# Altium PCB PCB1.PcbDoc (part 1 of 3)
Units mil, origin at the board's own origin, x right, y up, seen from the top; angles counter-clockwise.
Board outline 6299 x 3937 mil, 12 copper layers (TopLayer, VCC, GROUND, MidLayer1, MidLayer2, MidLayer3, MidLayer4, MidLayer5, MidLayer6, MidLayer7, MidLayer8, BottomLayer); 299 components, 467 nets, 2148 pads, 429 vias.
Unrouted connection lines stored in the file: 461.
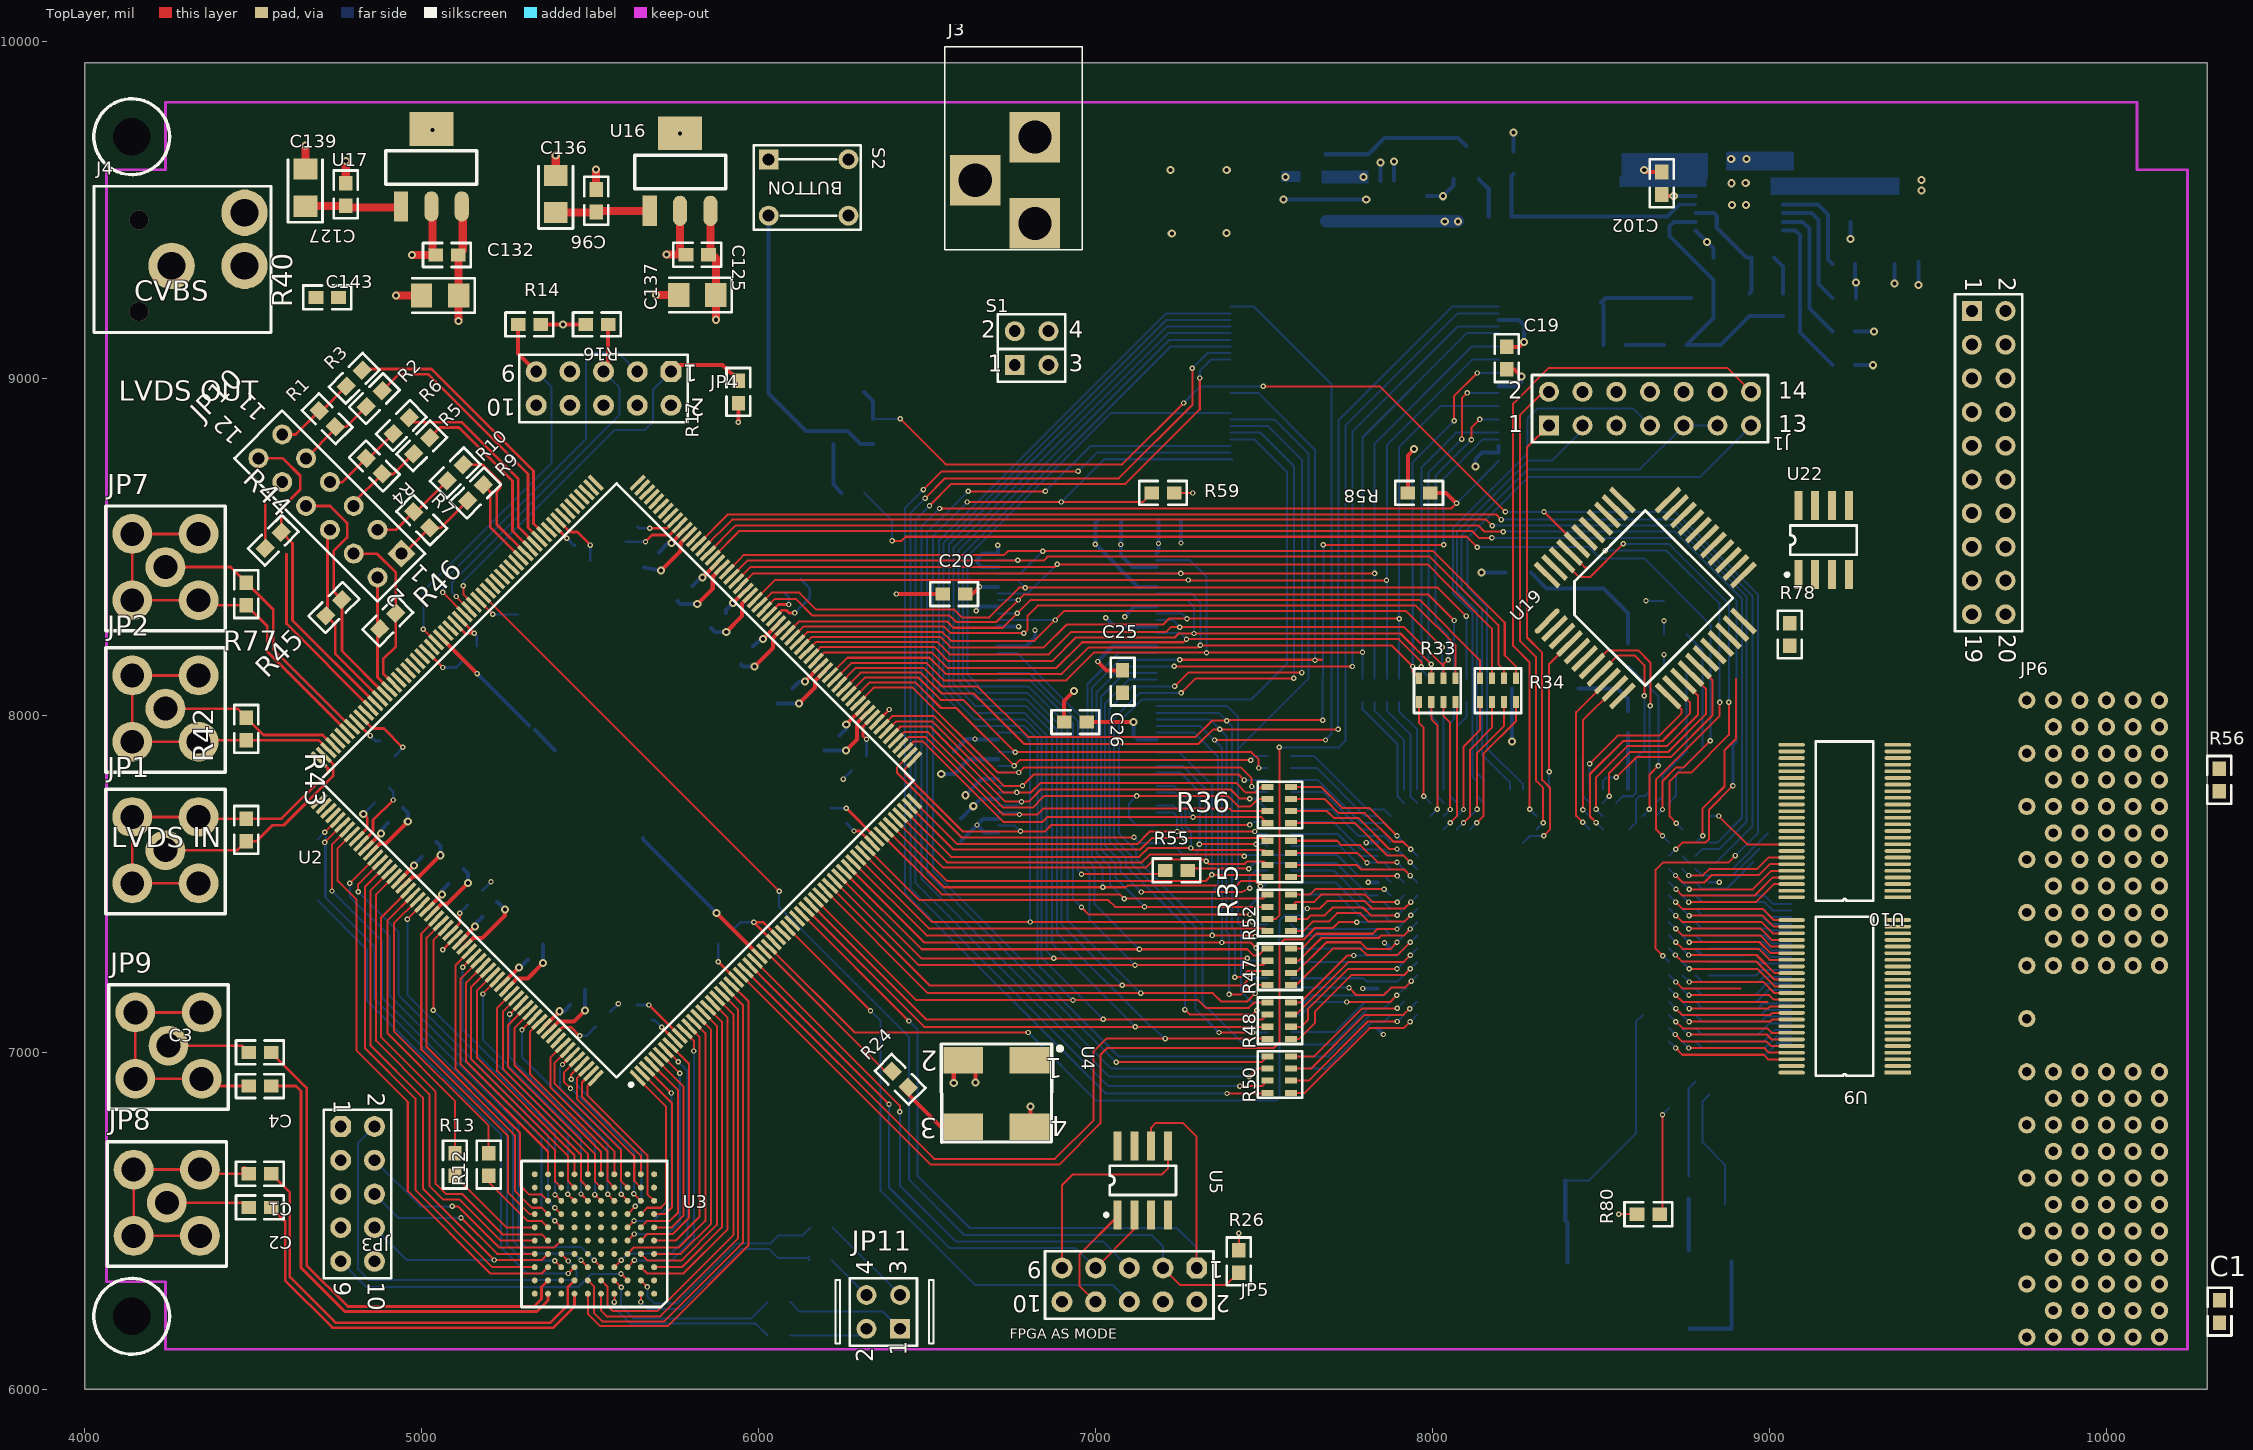
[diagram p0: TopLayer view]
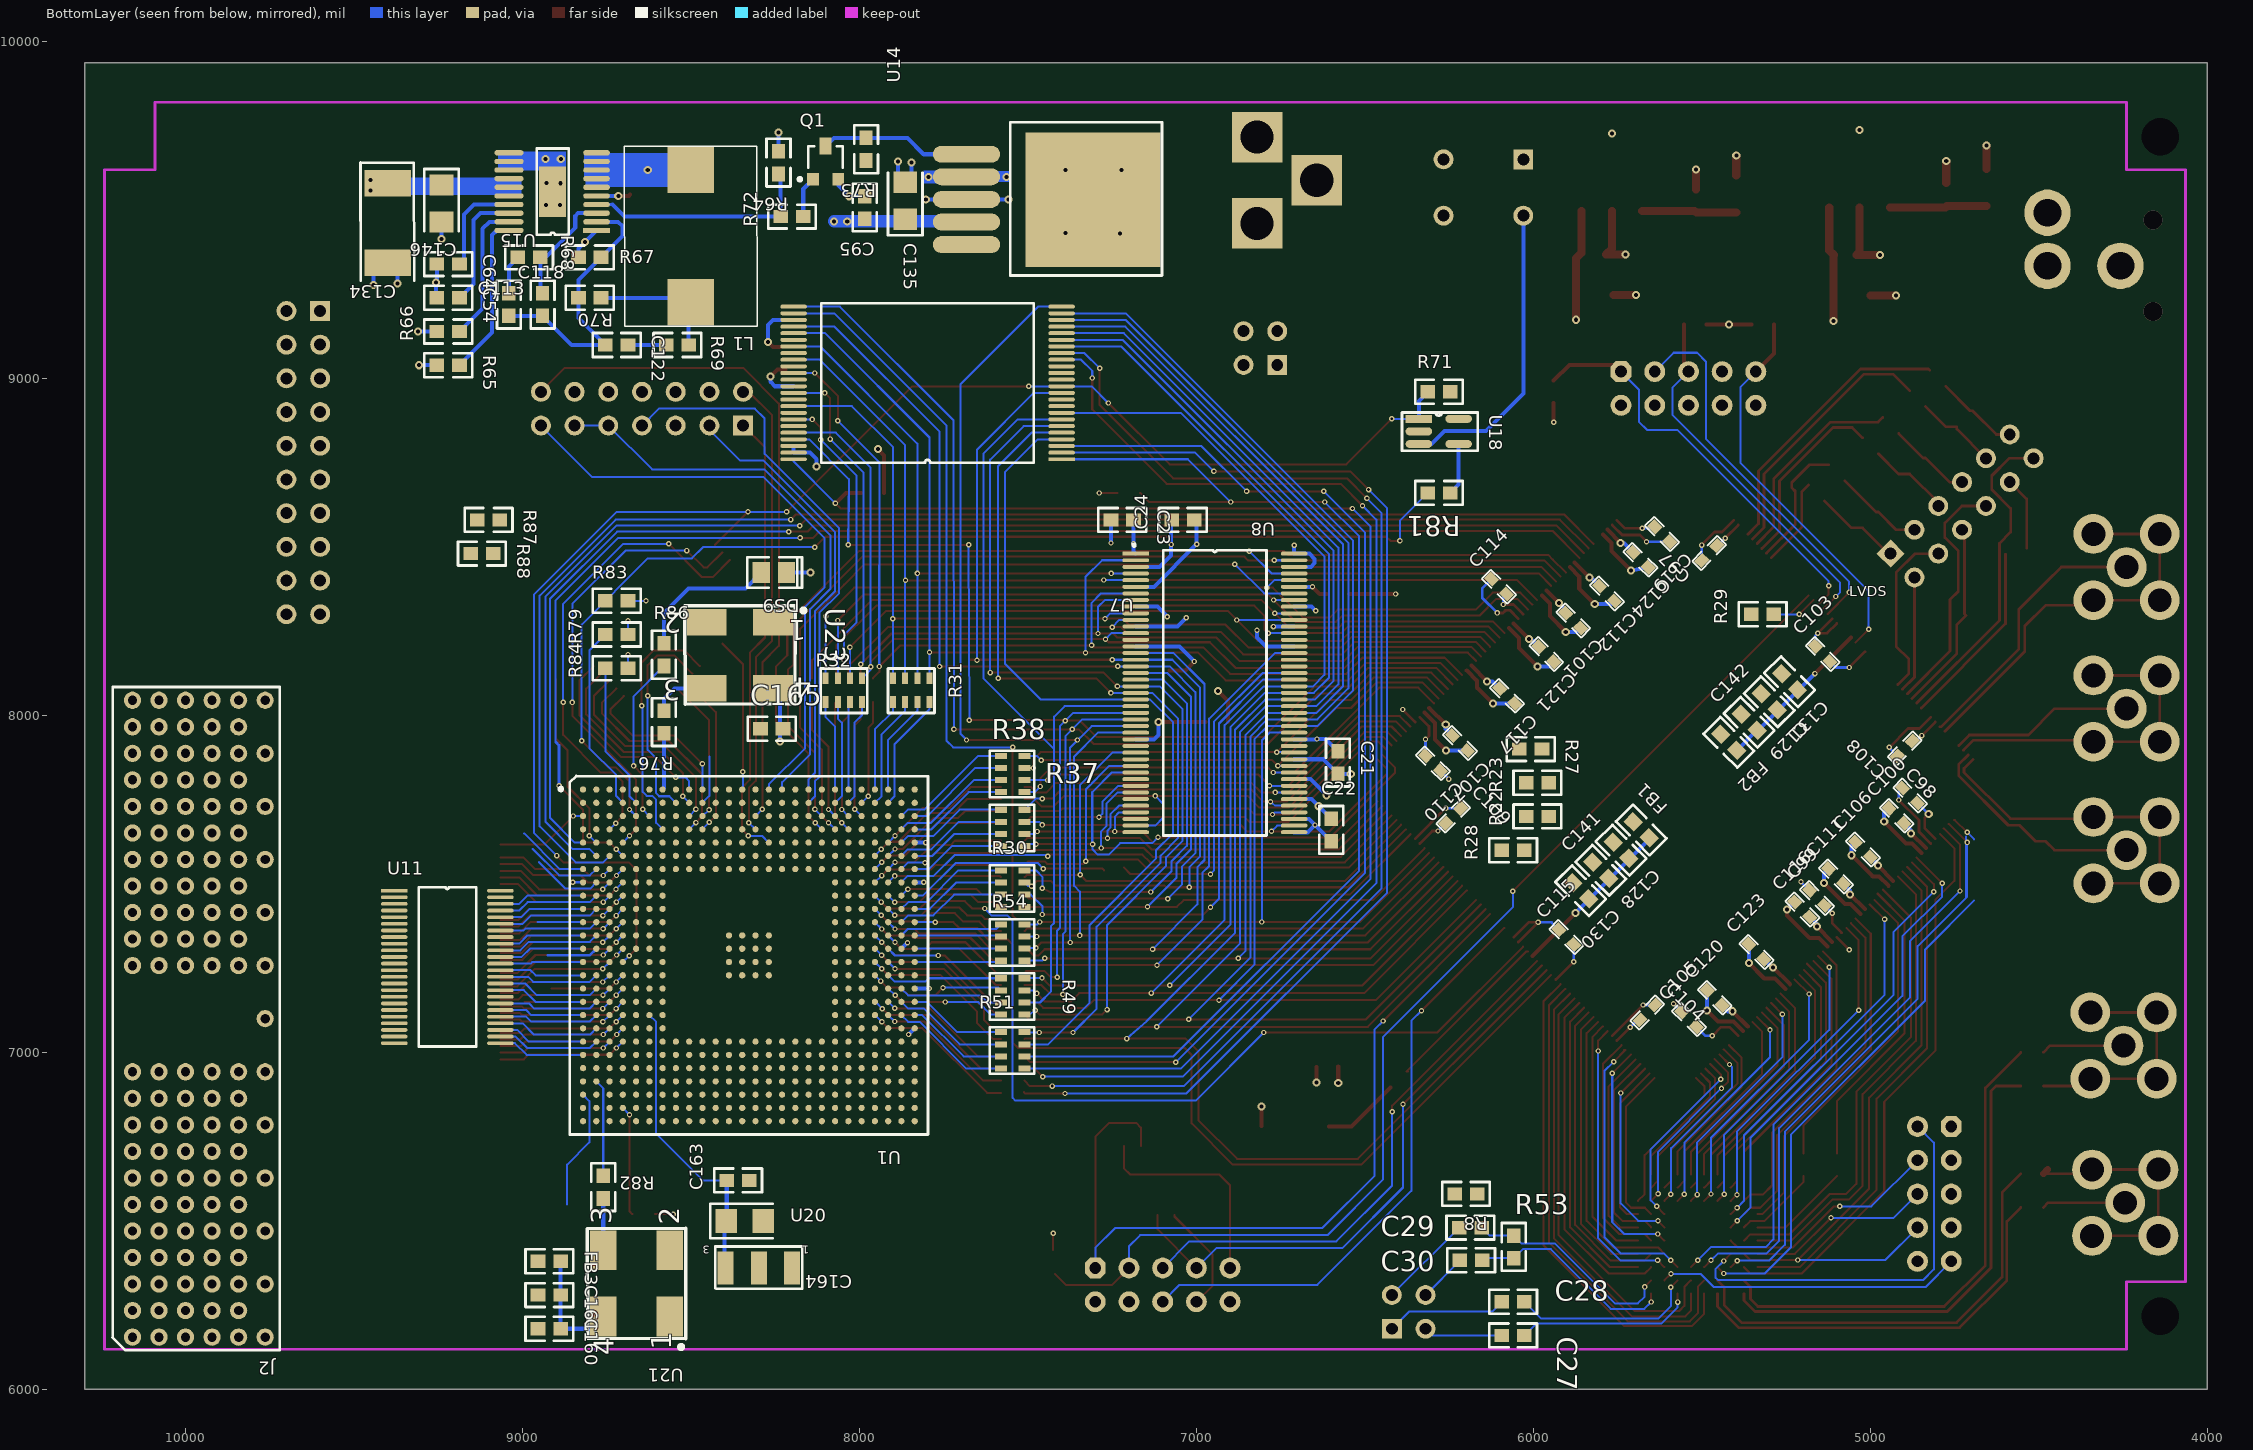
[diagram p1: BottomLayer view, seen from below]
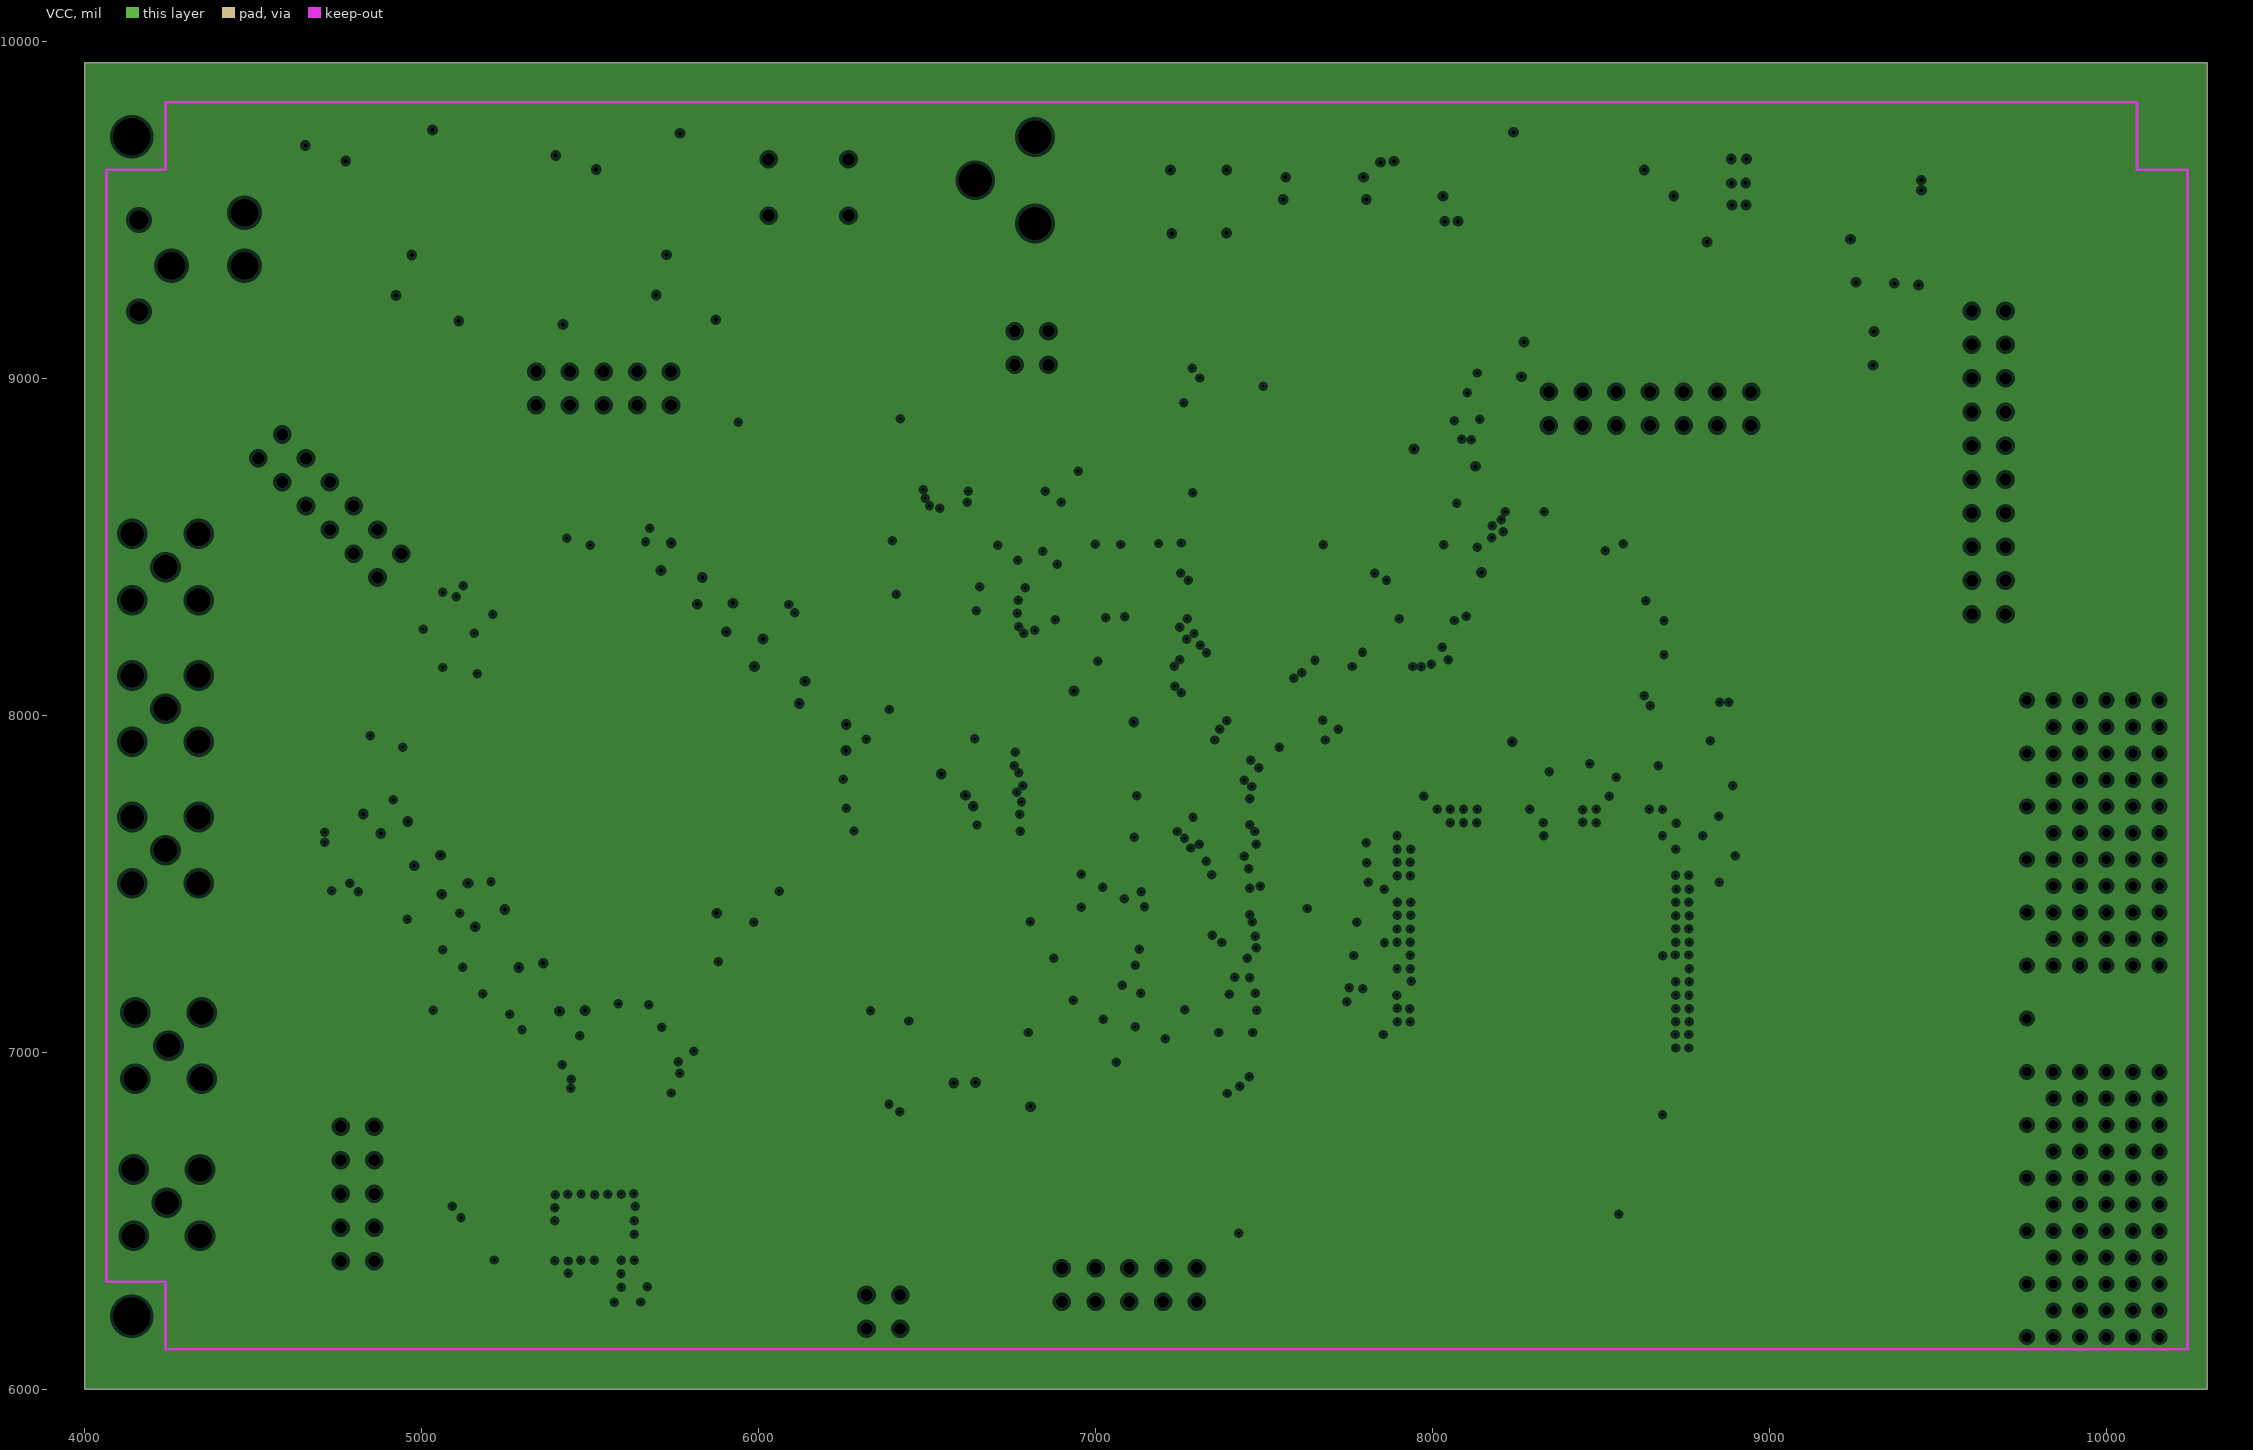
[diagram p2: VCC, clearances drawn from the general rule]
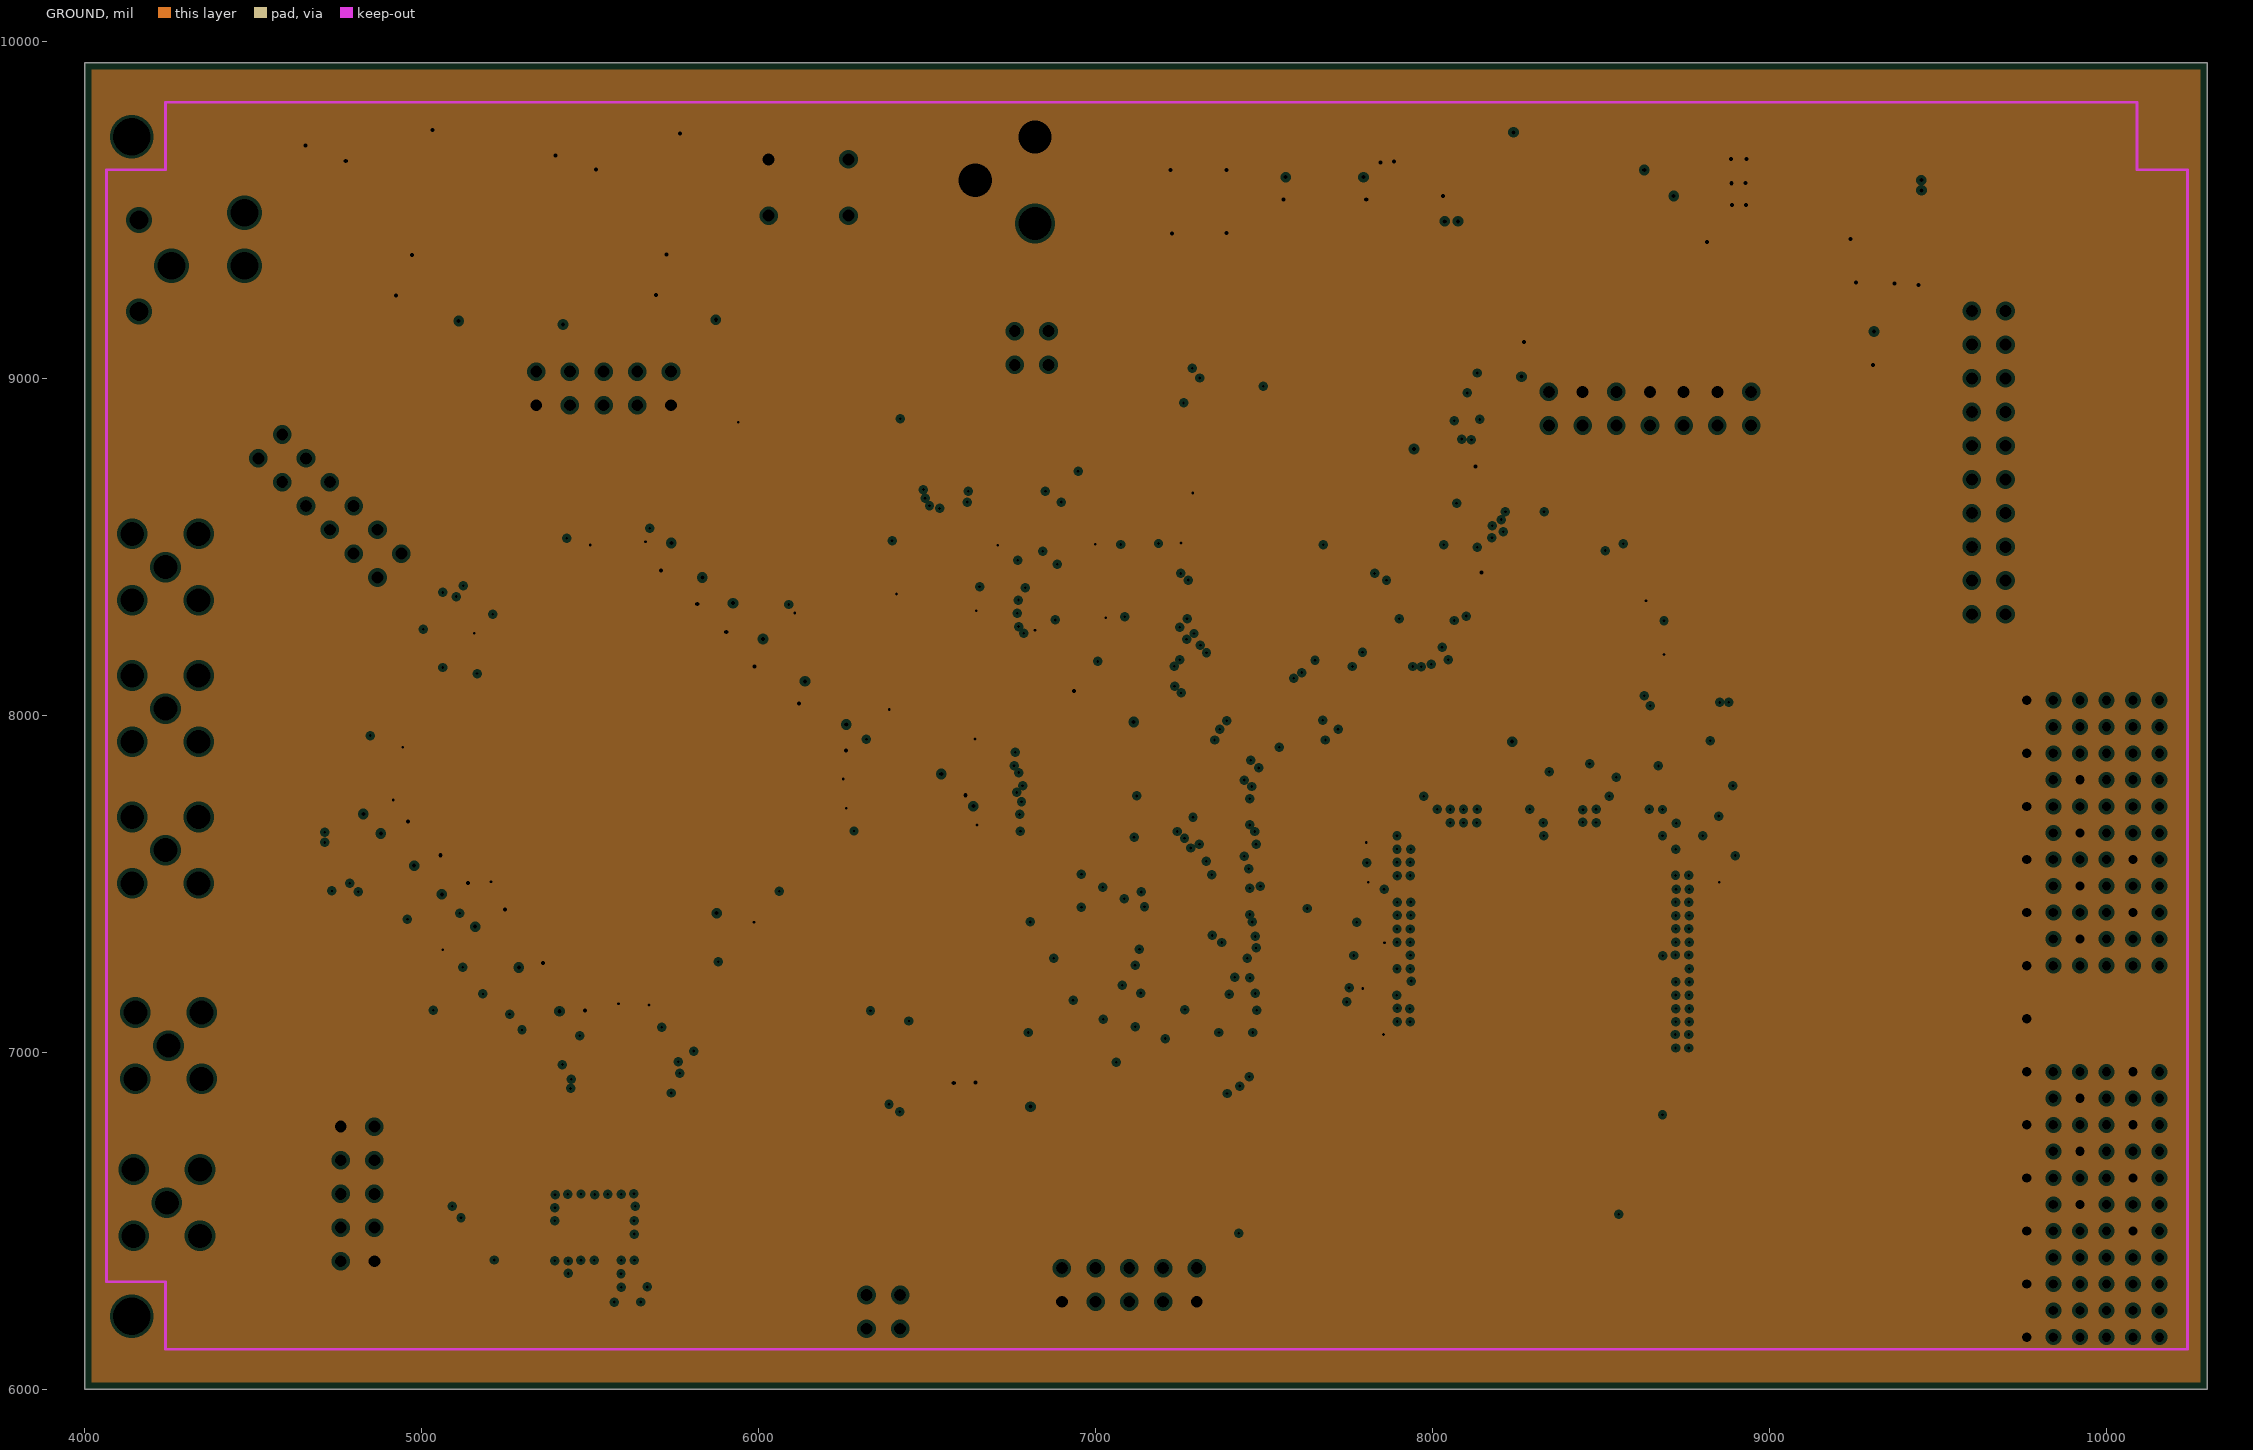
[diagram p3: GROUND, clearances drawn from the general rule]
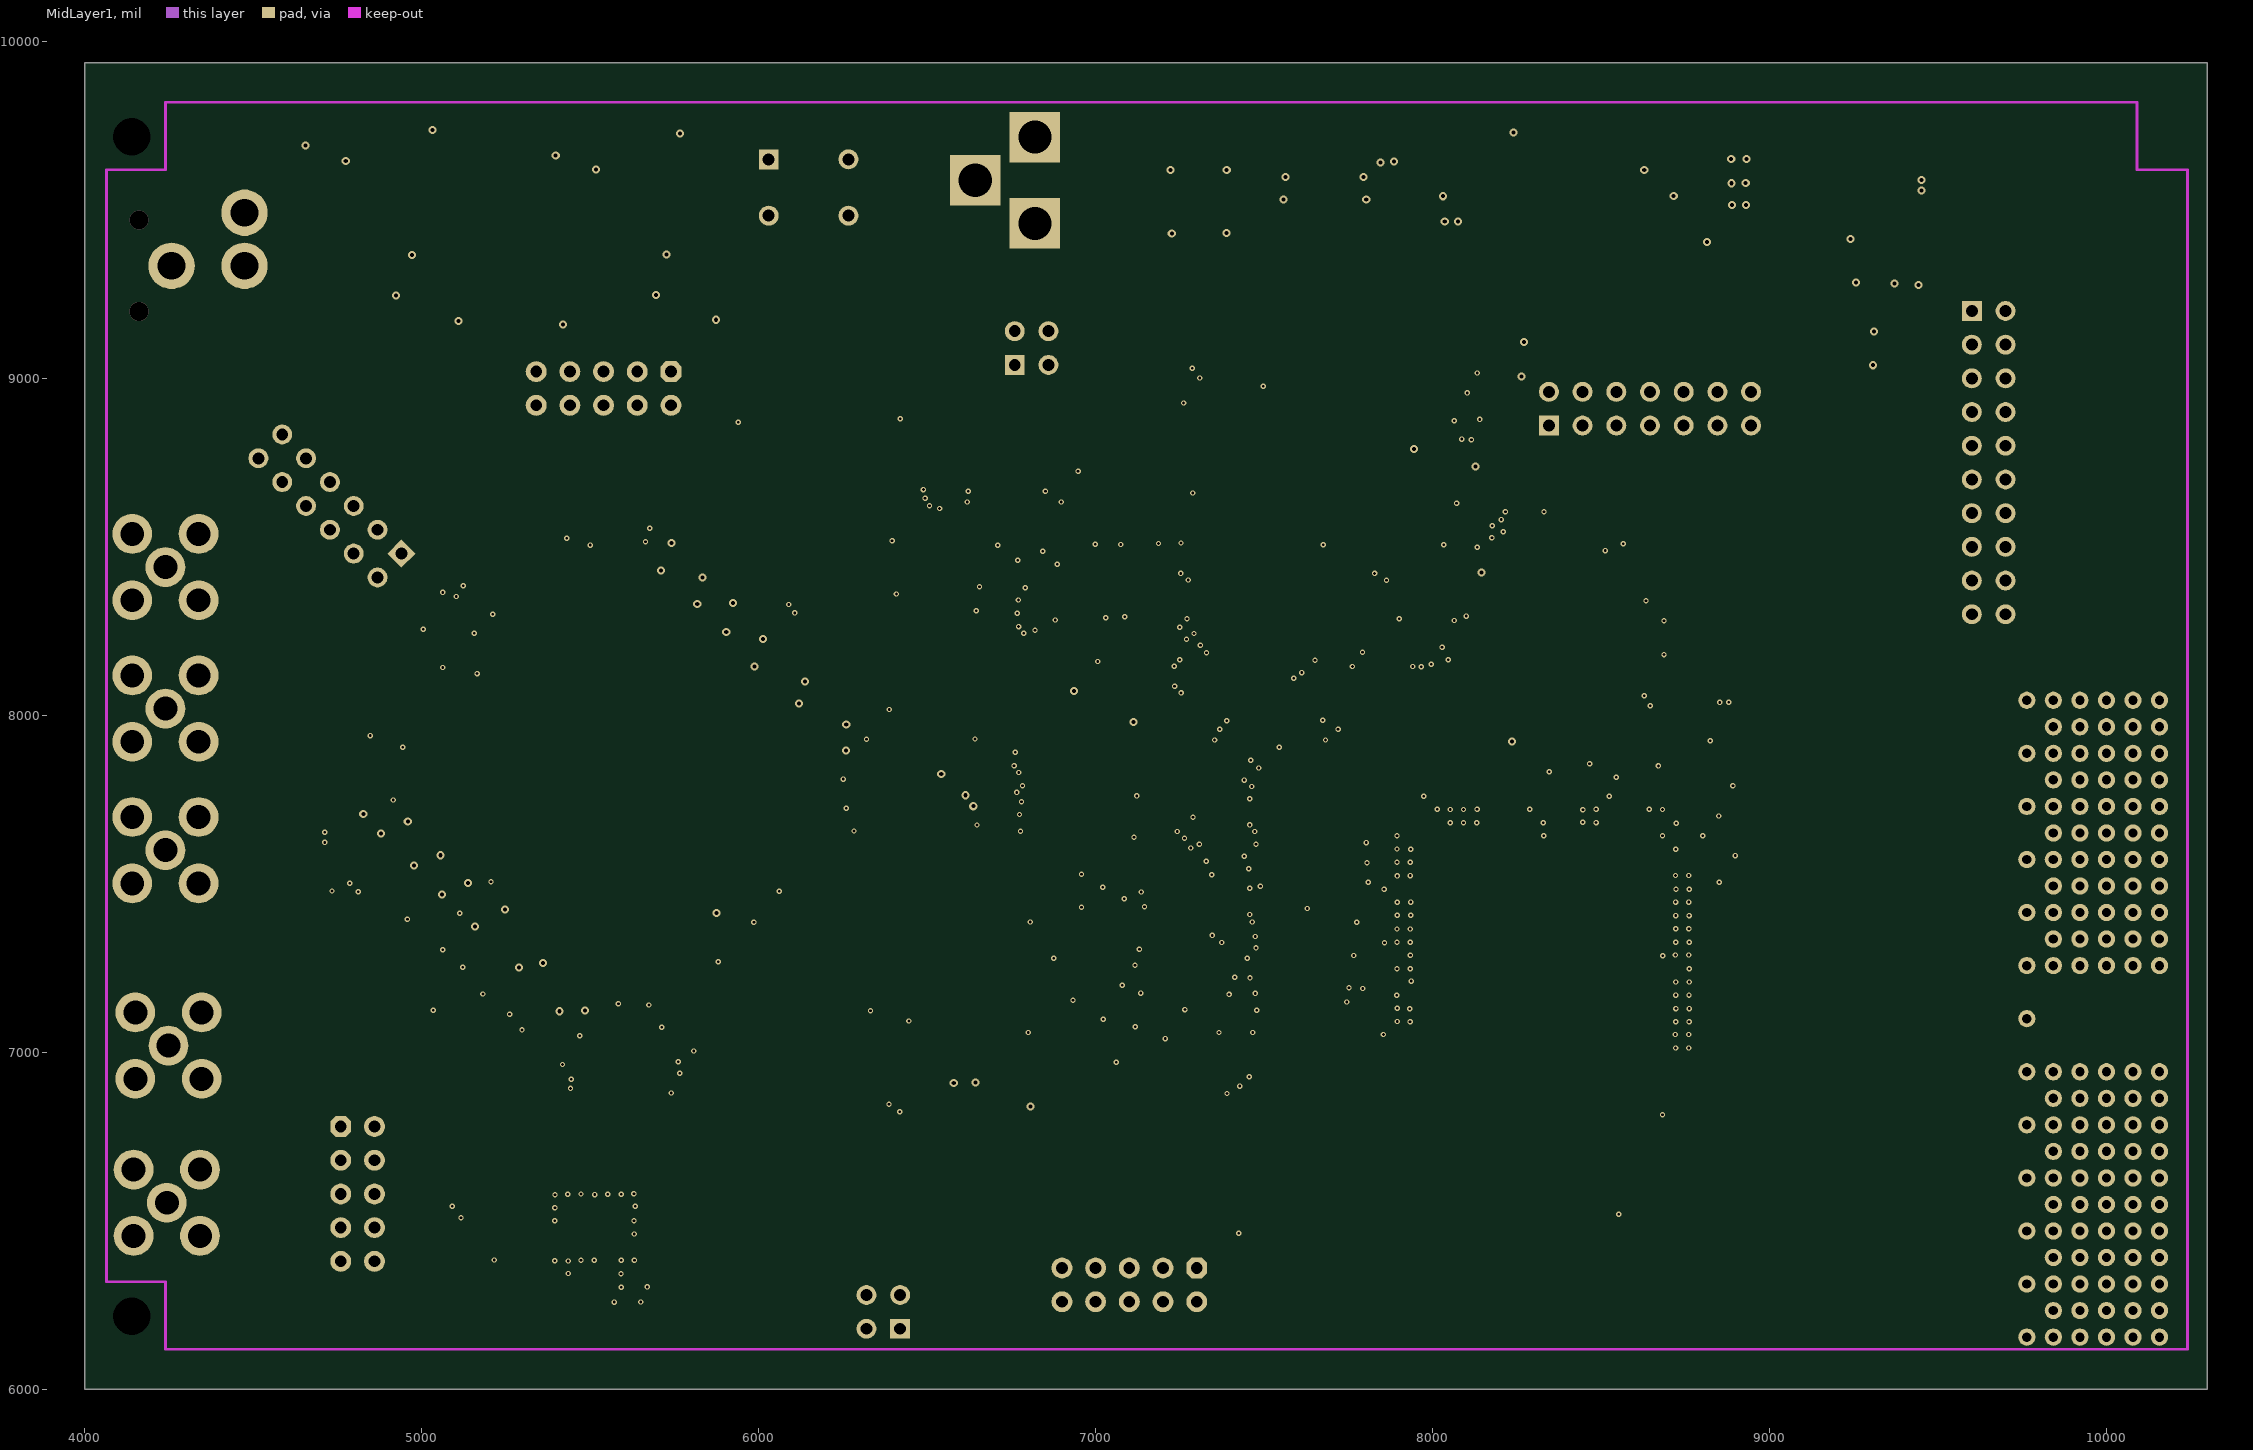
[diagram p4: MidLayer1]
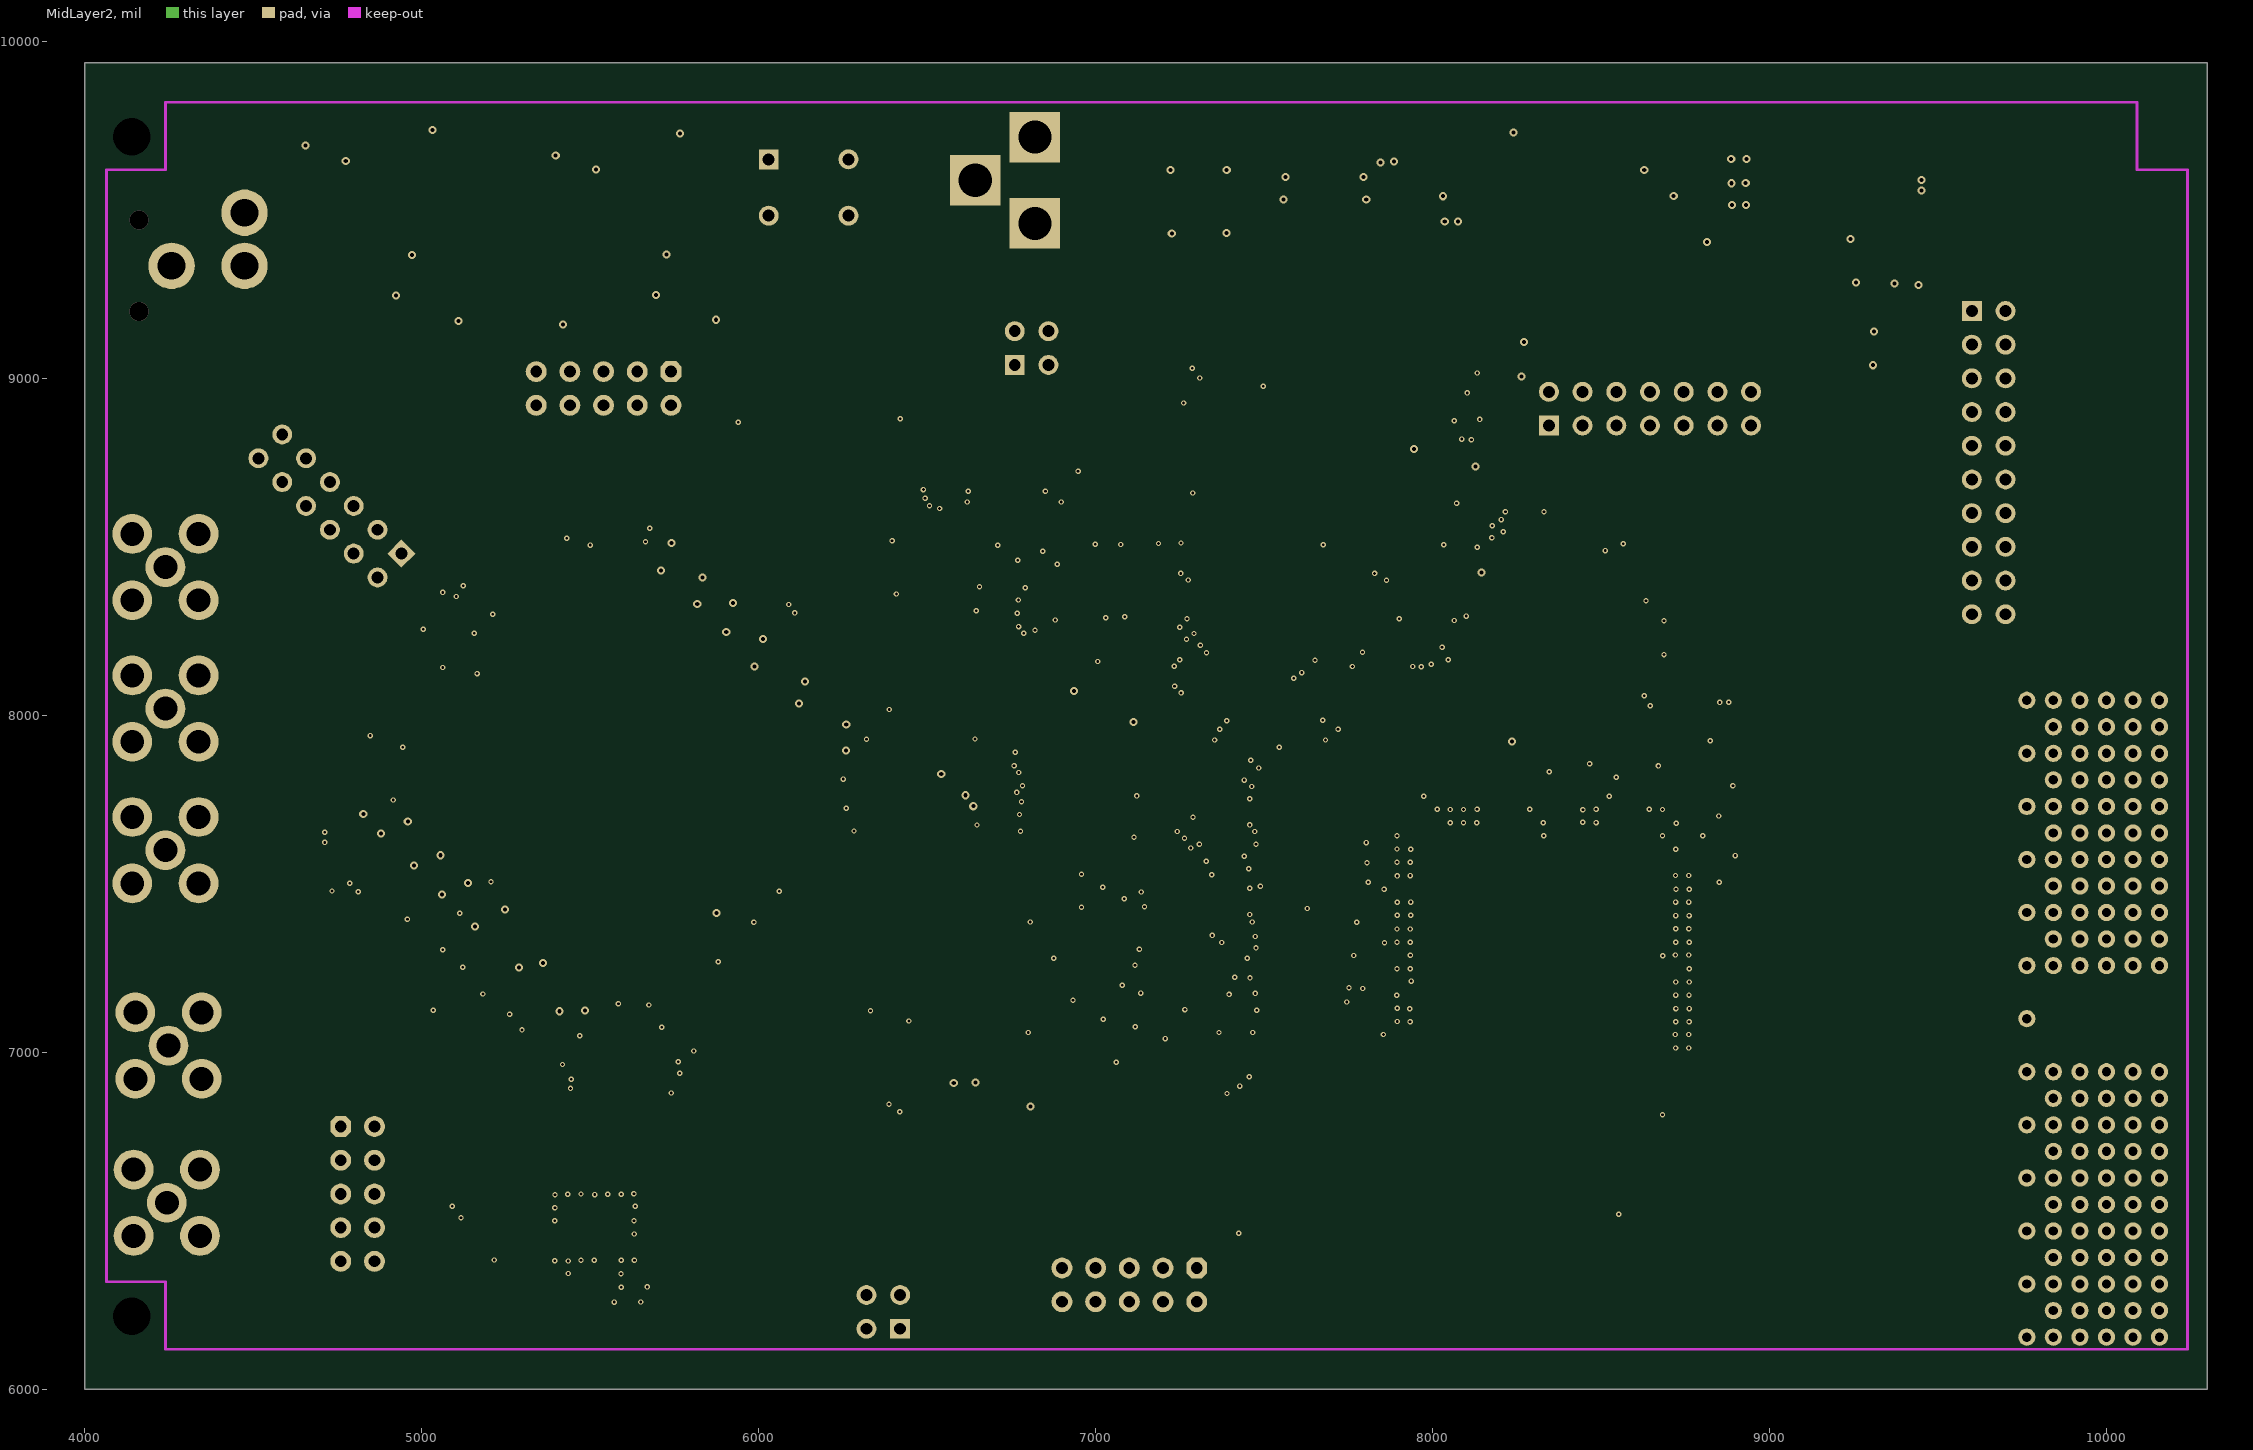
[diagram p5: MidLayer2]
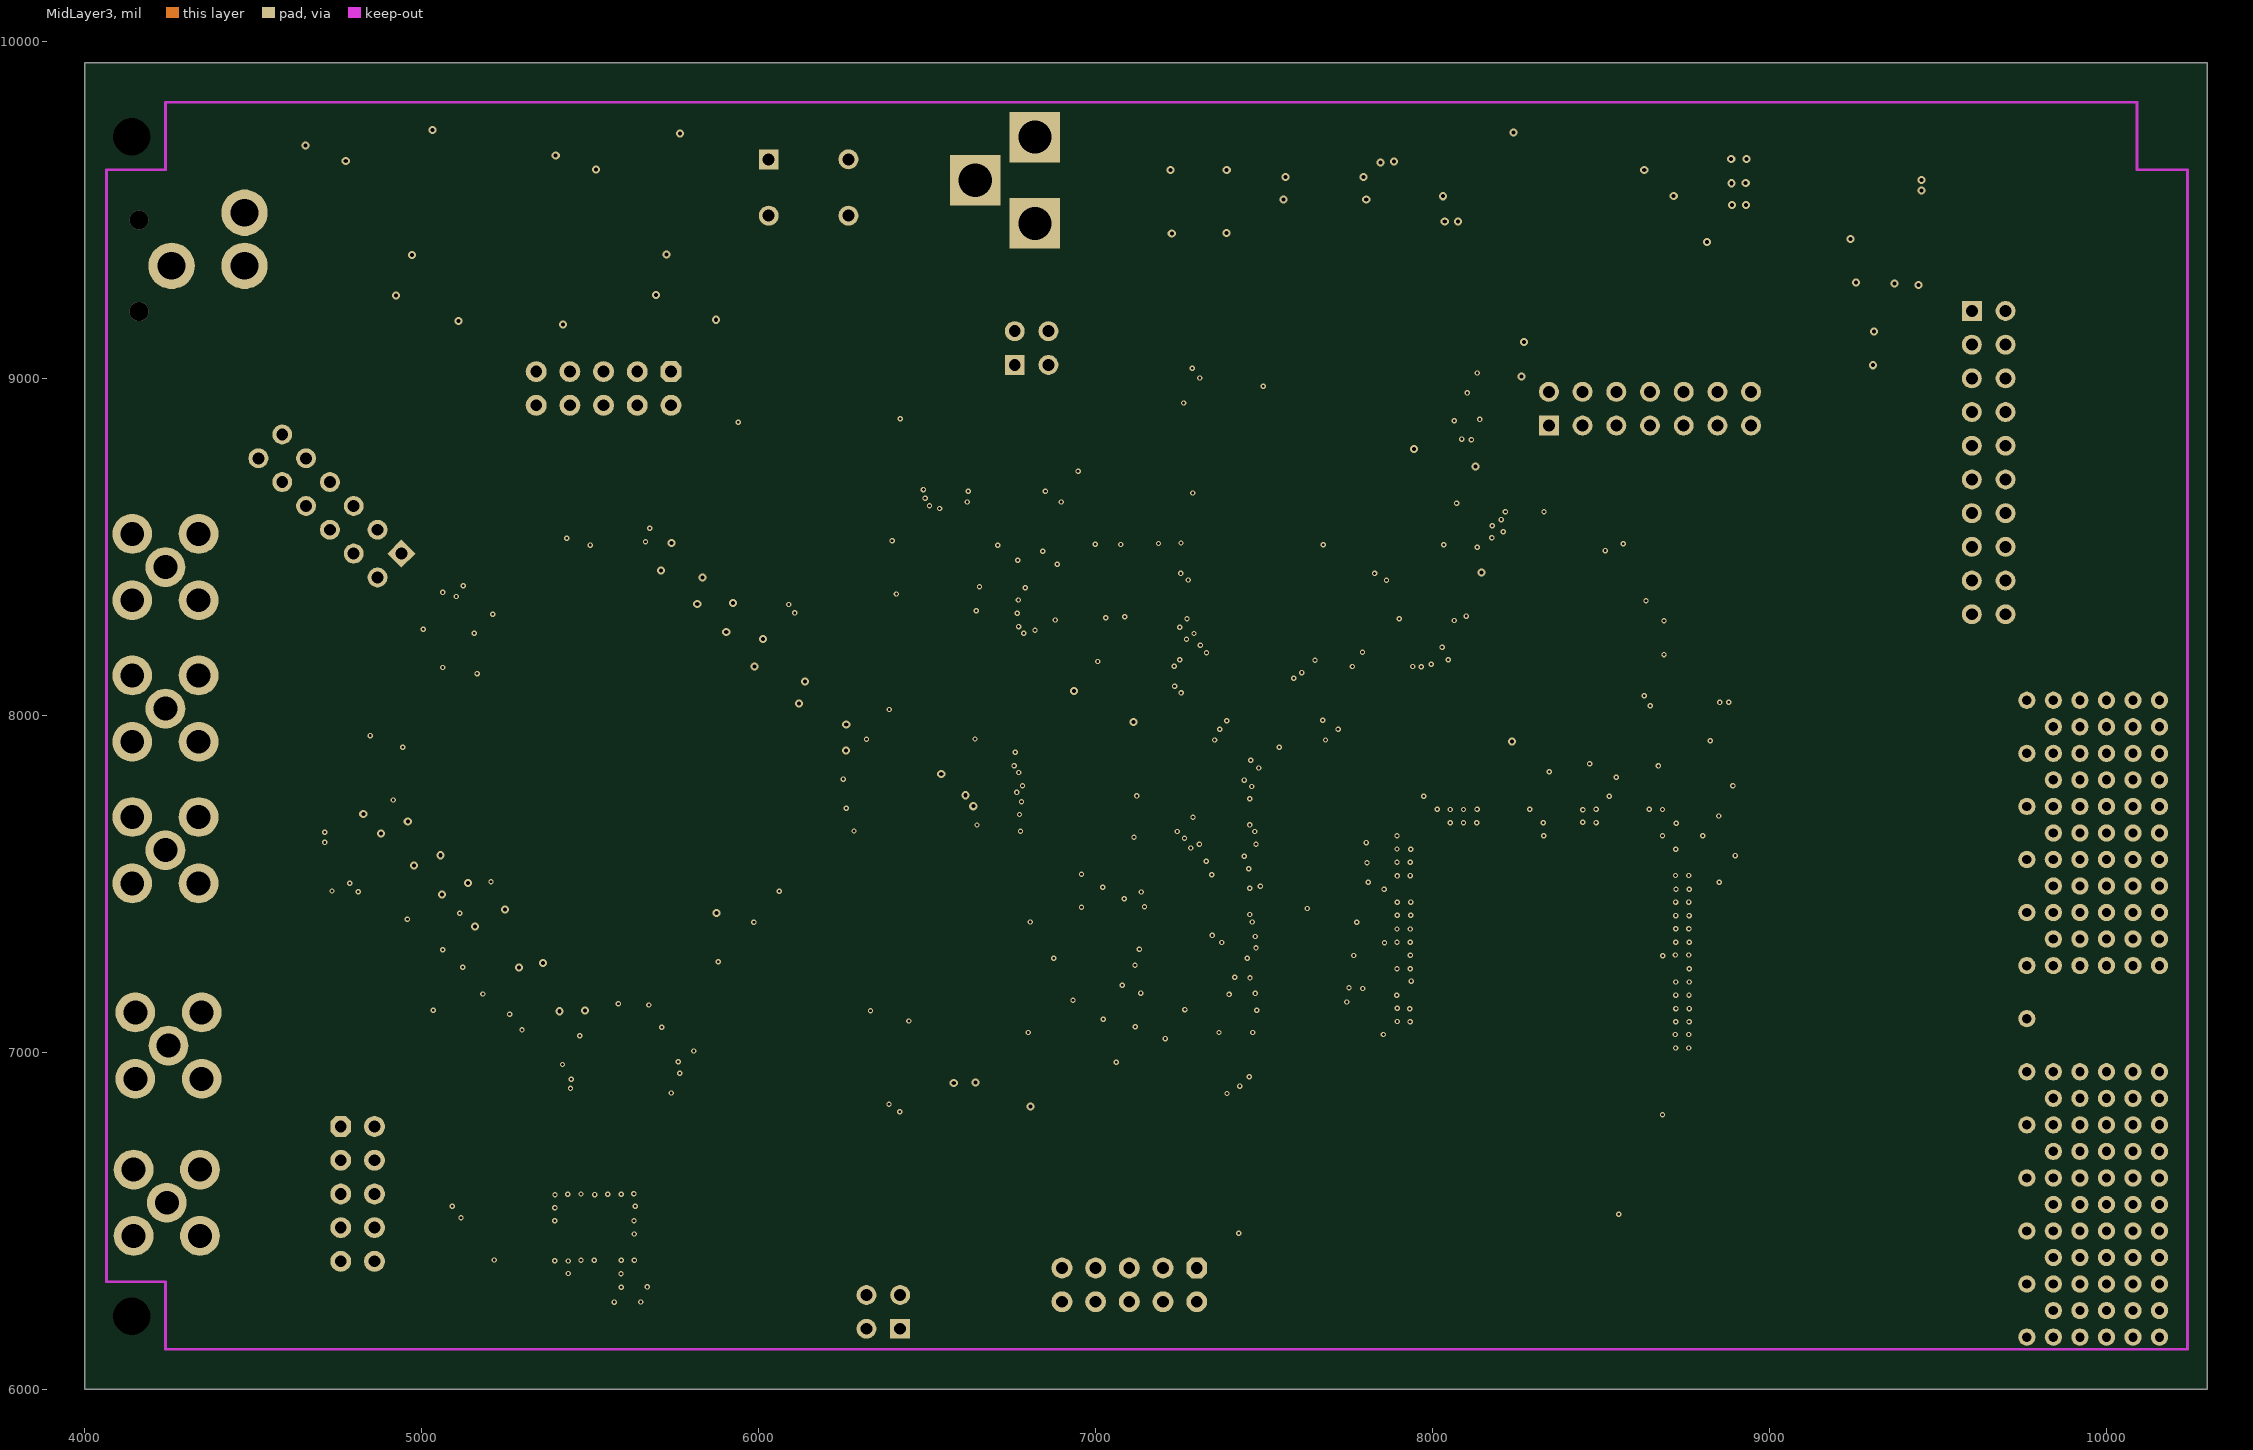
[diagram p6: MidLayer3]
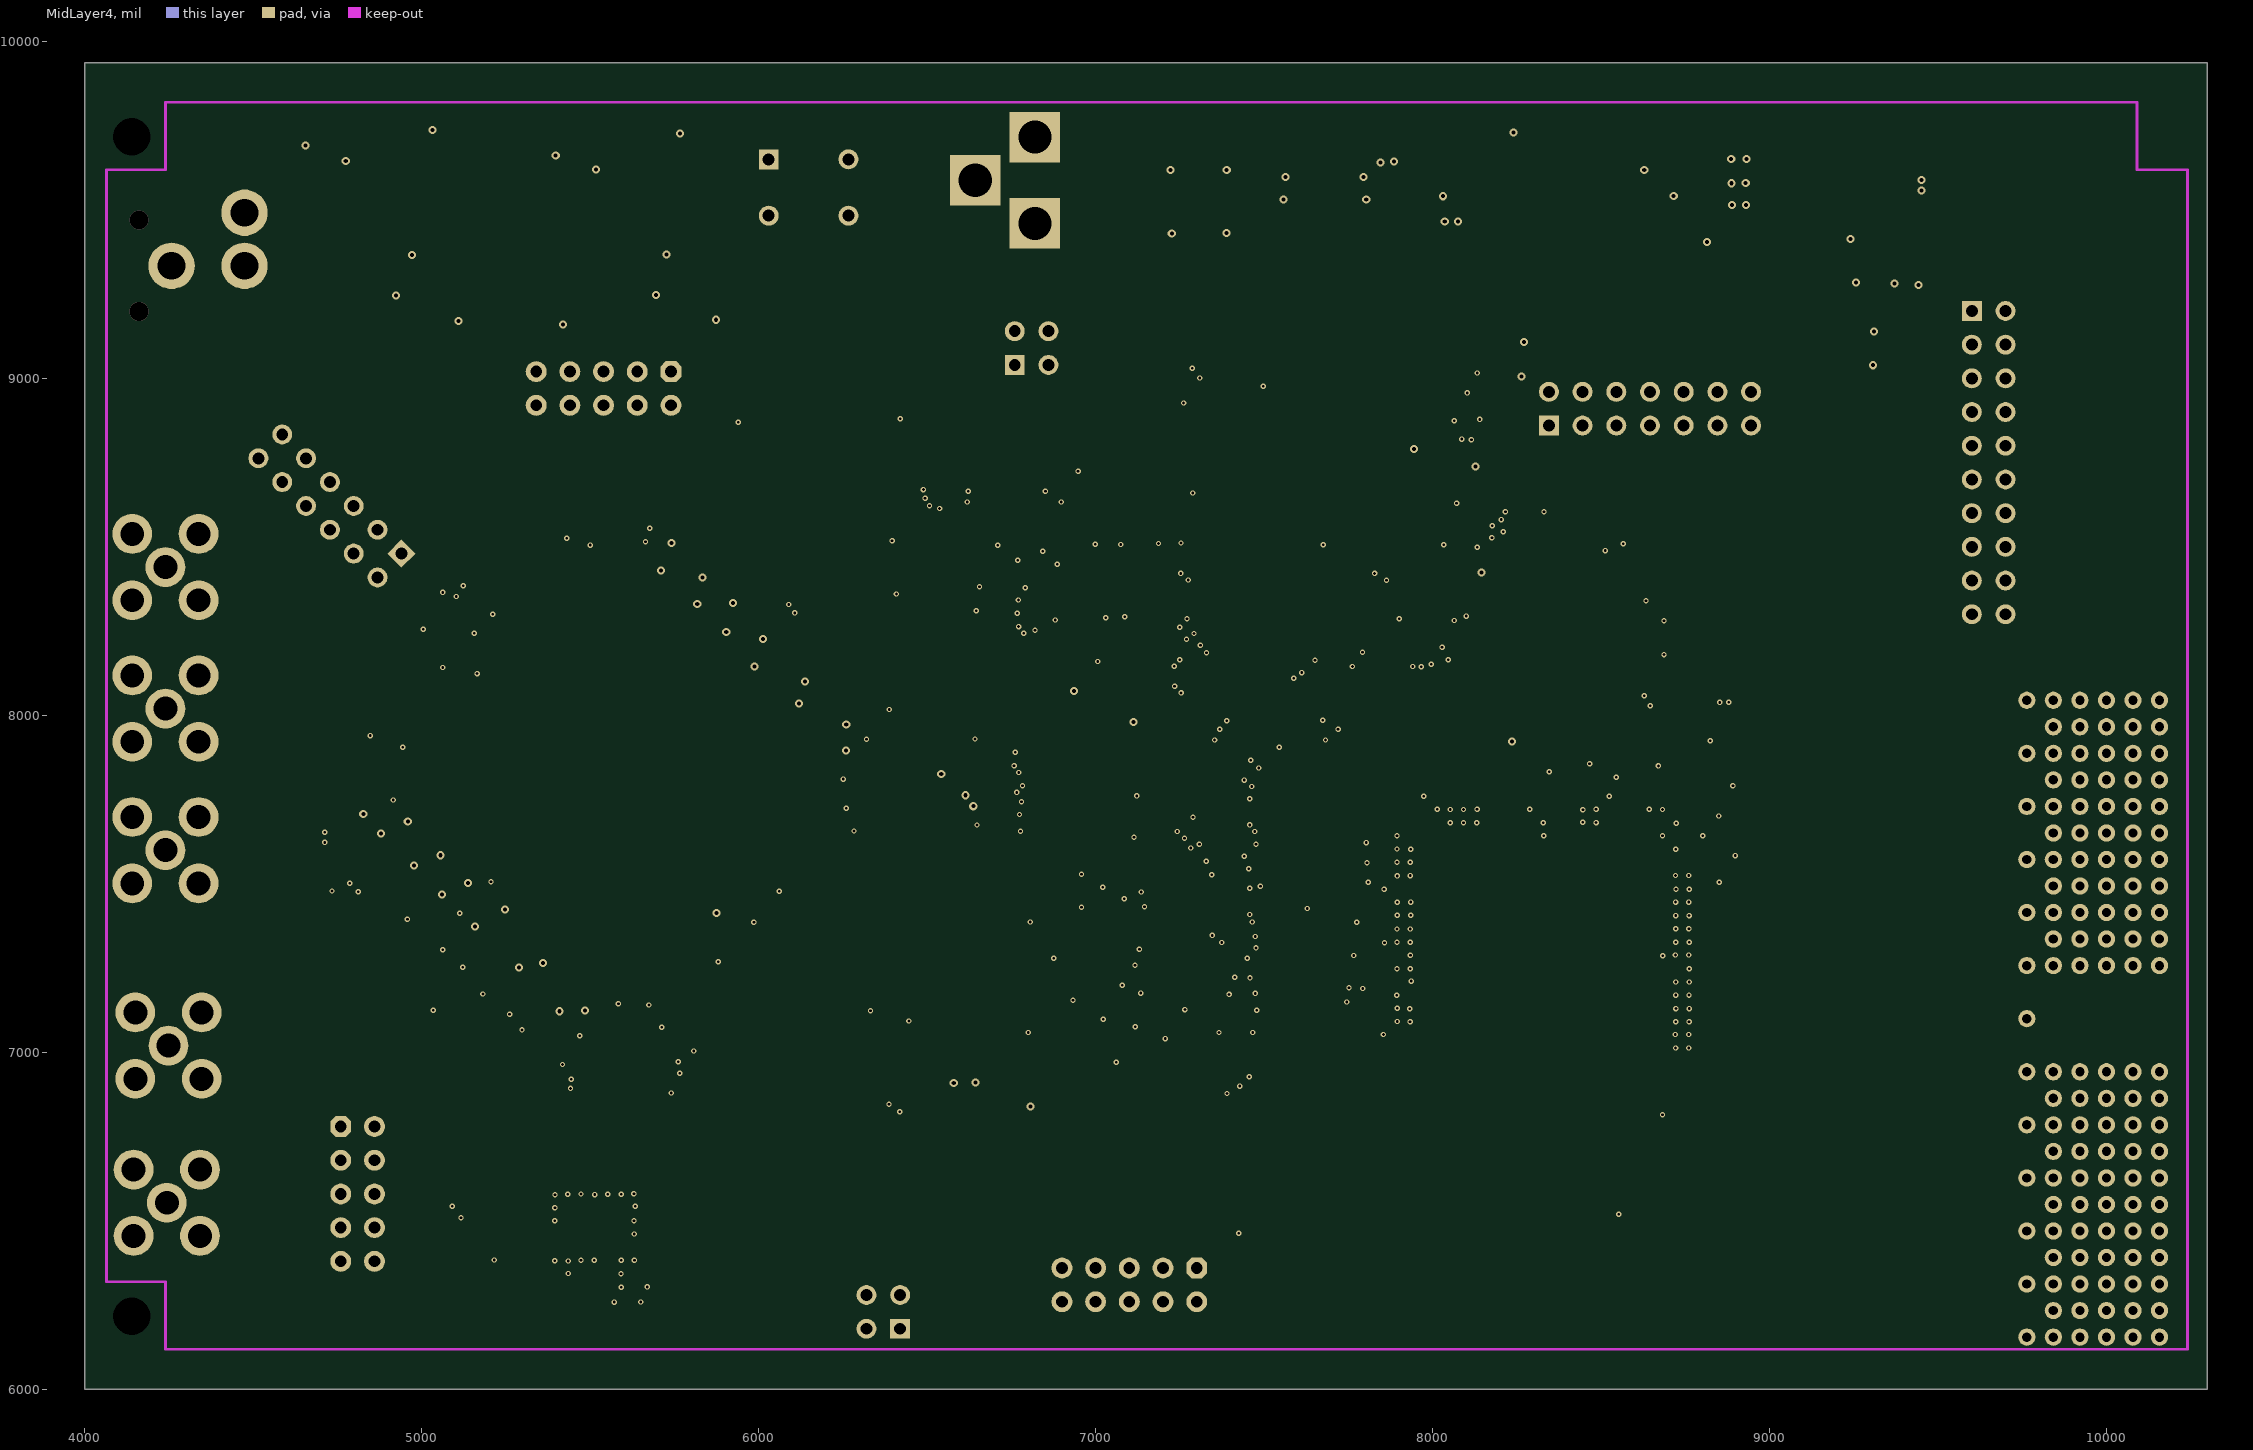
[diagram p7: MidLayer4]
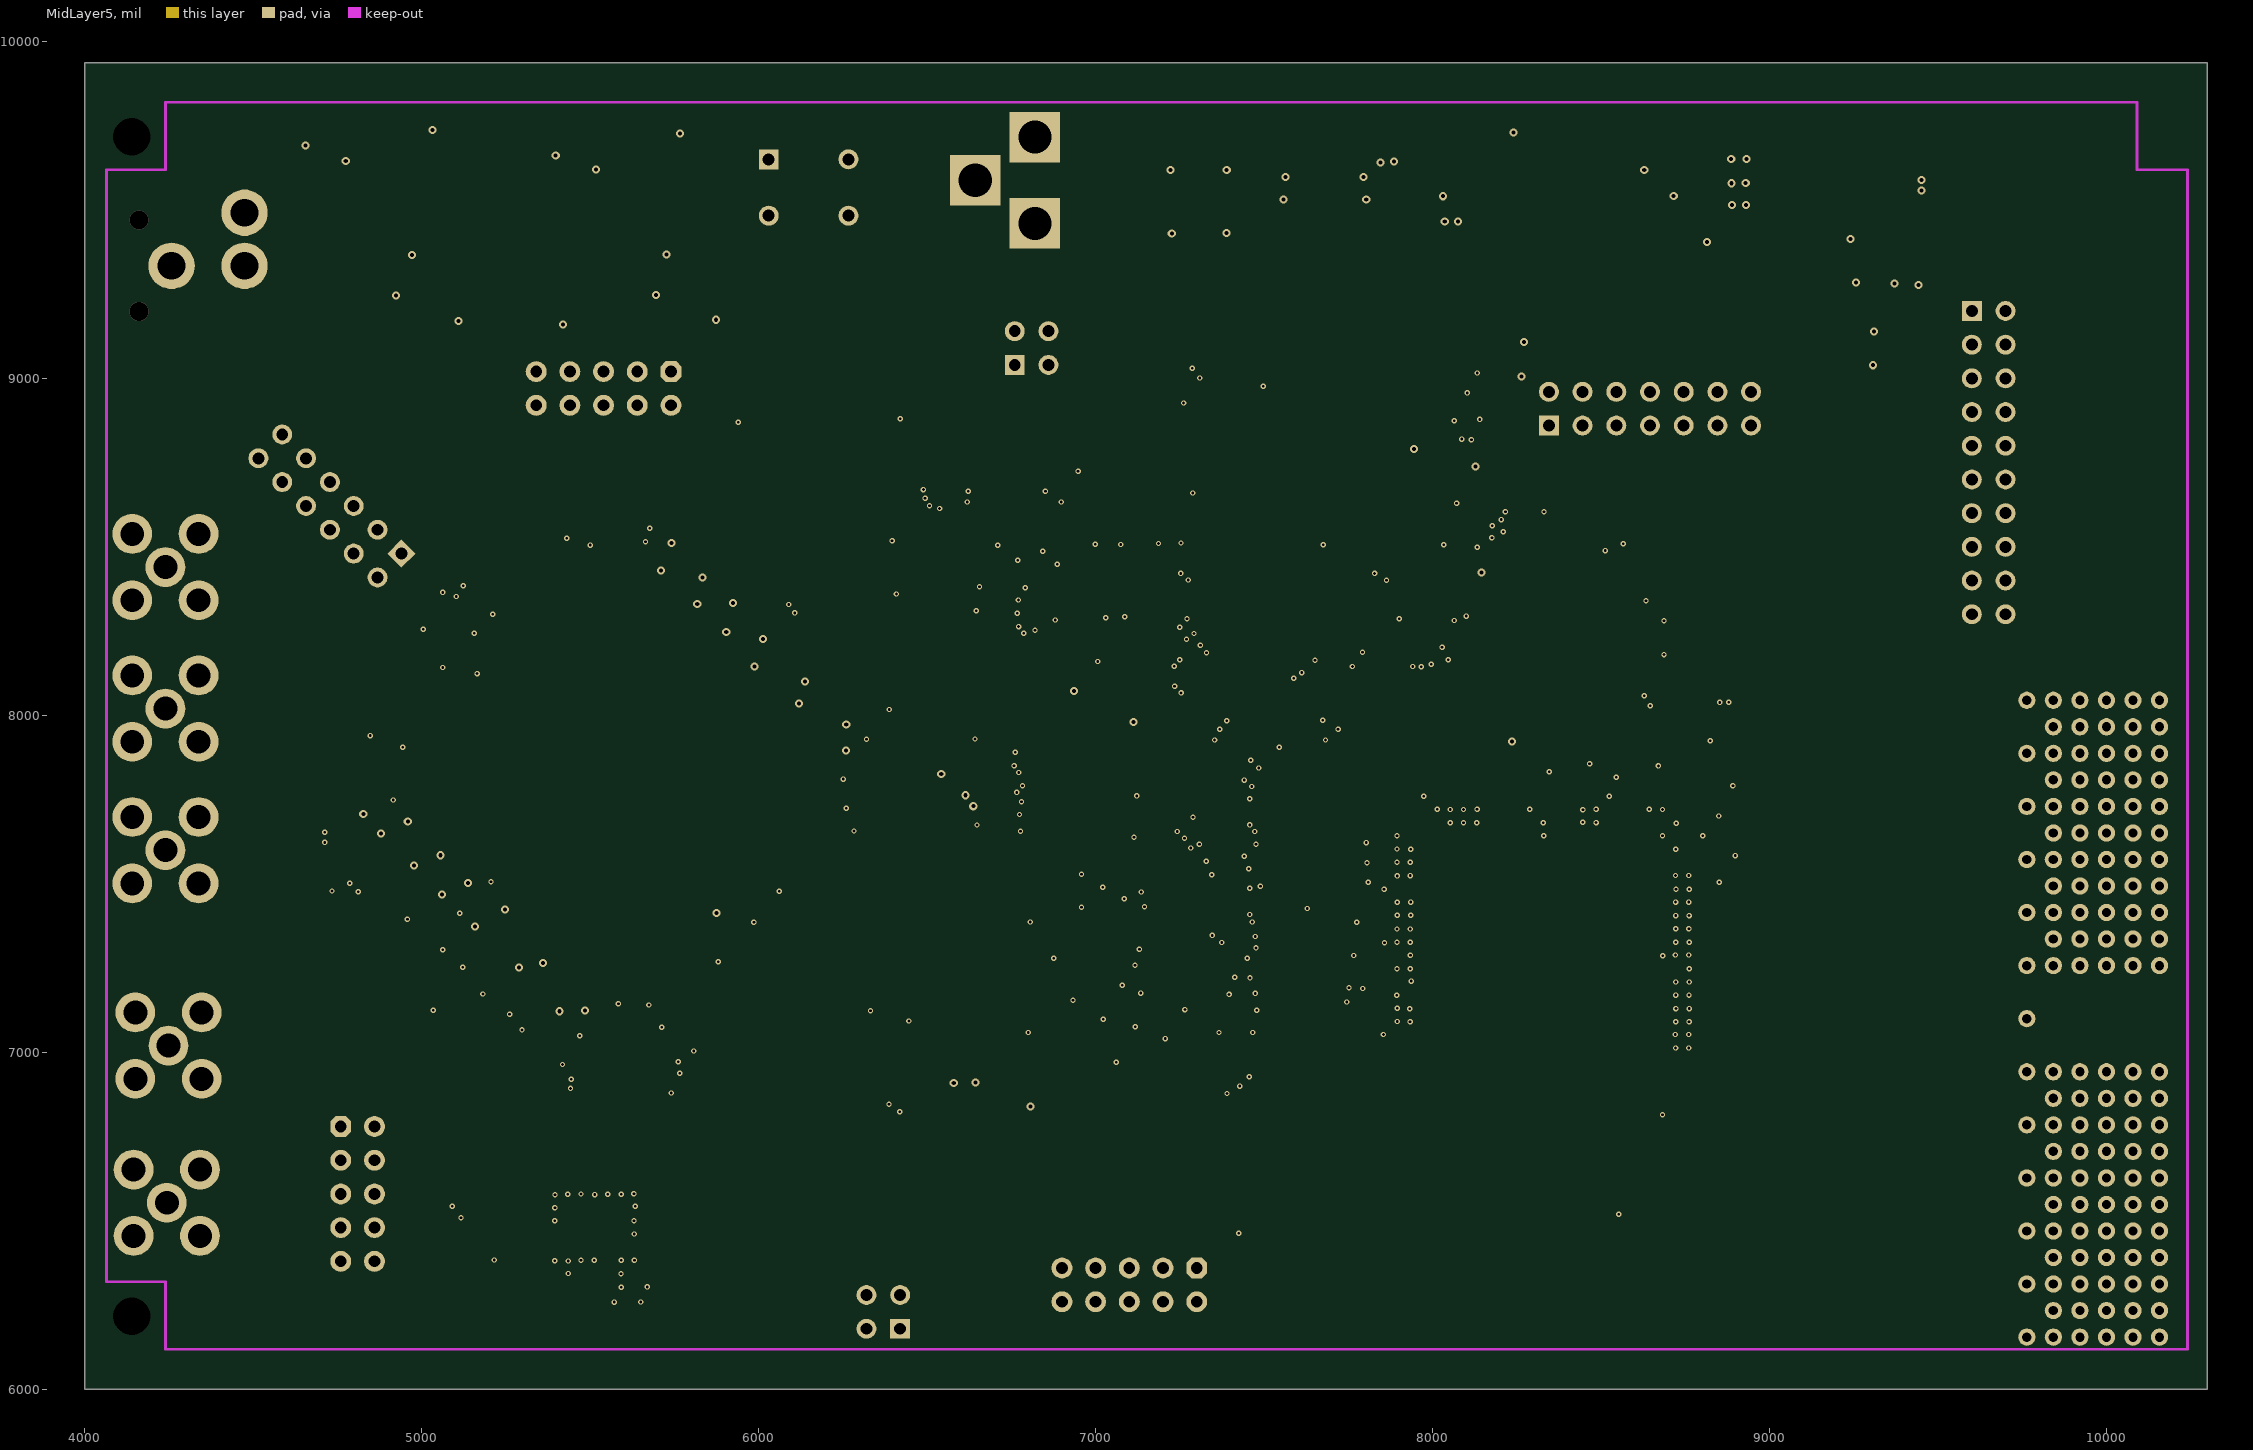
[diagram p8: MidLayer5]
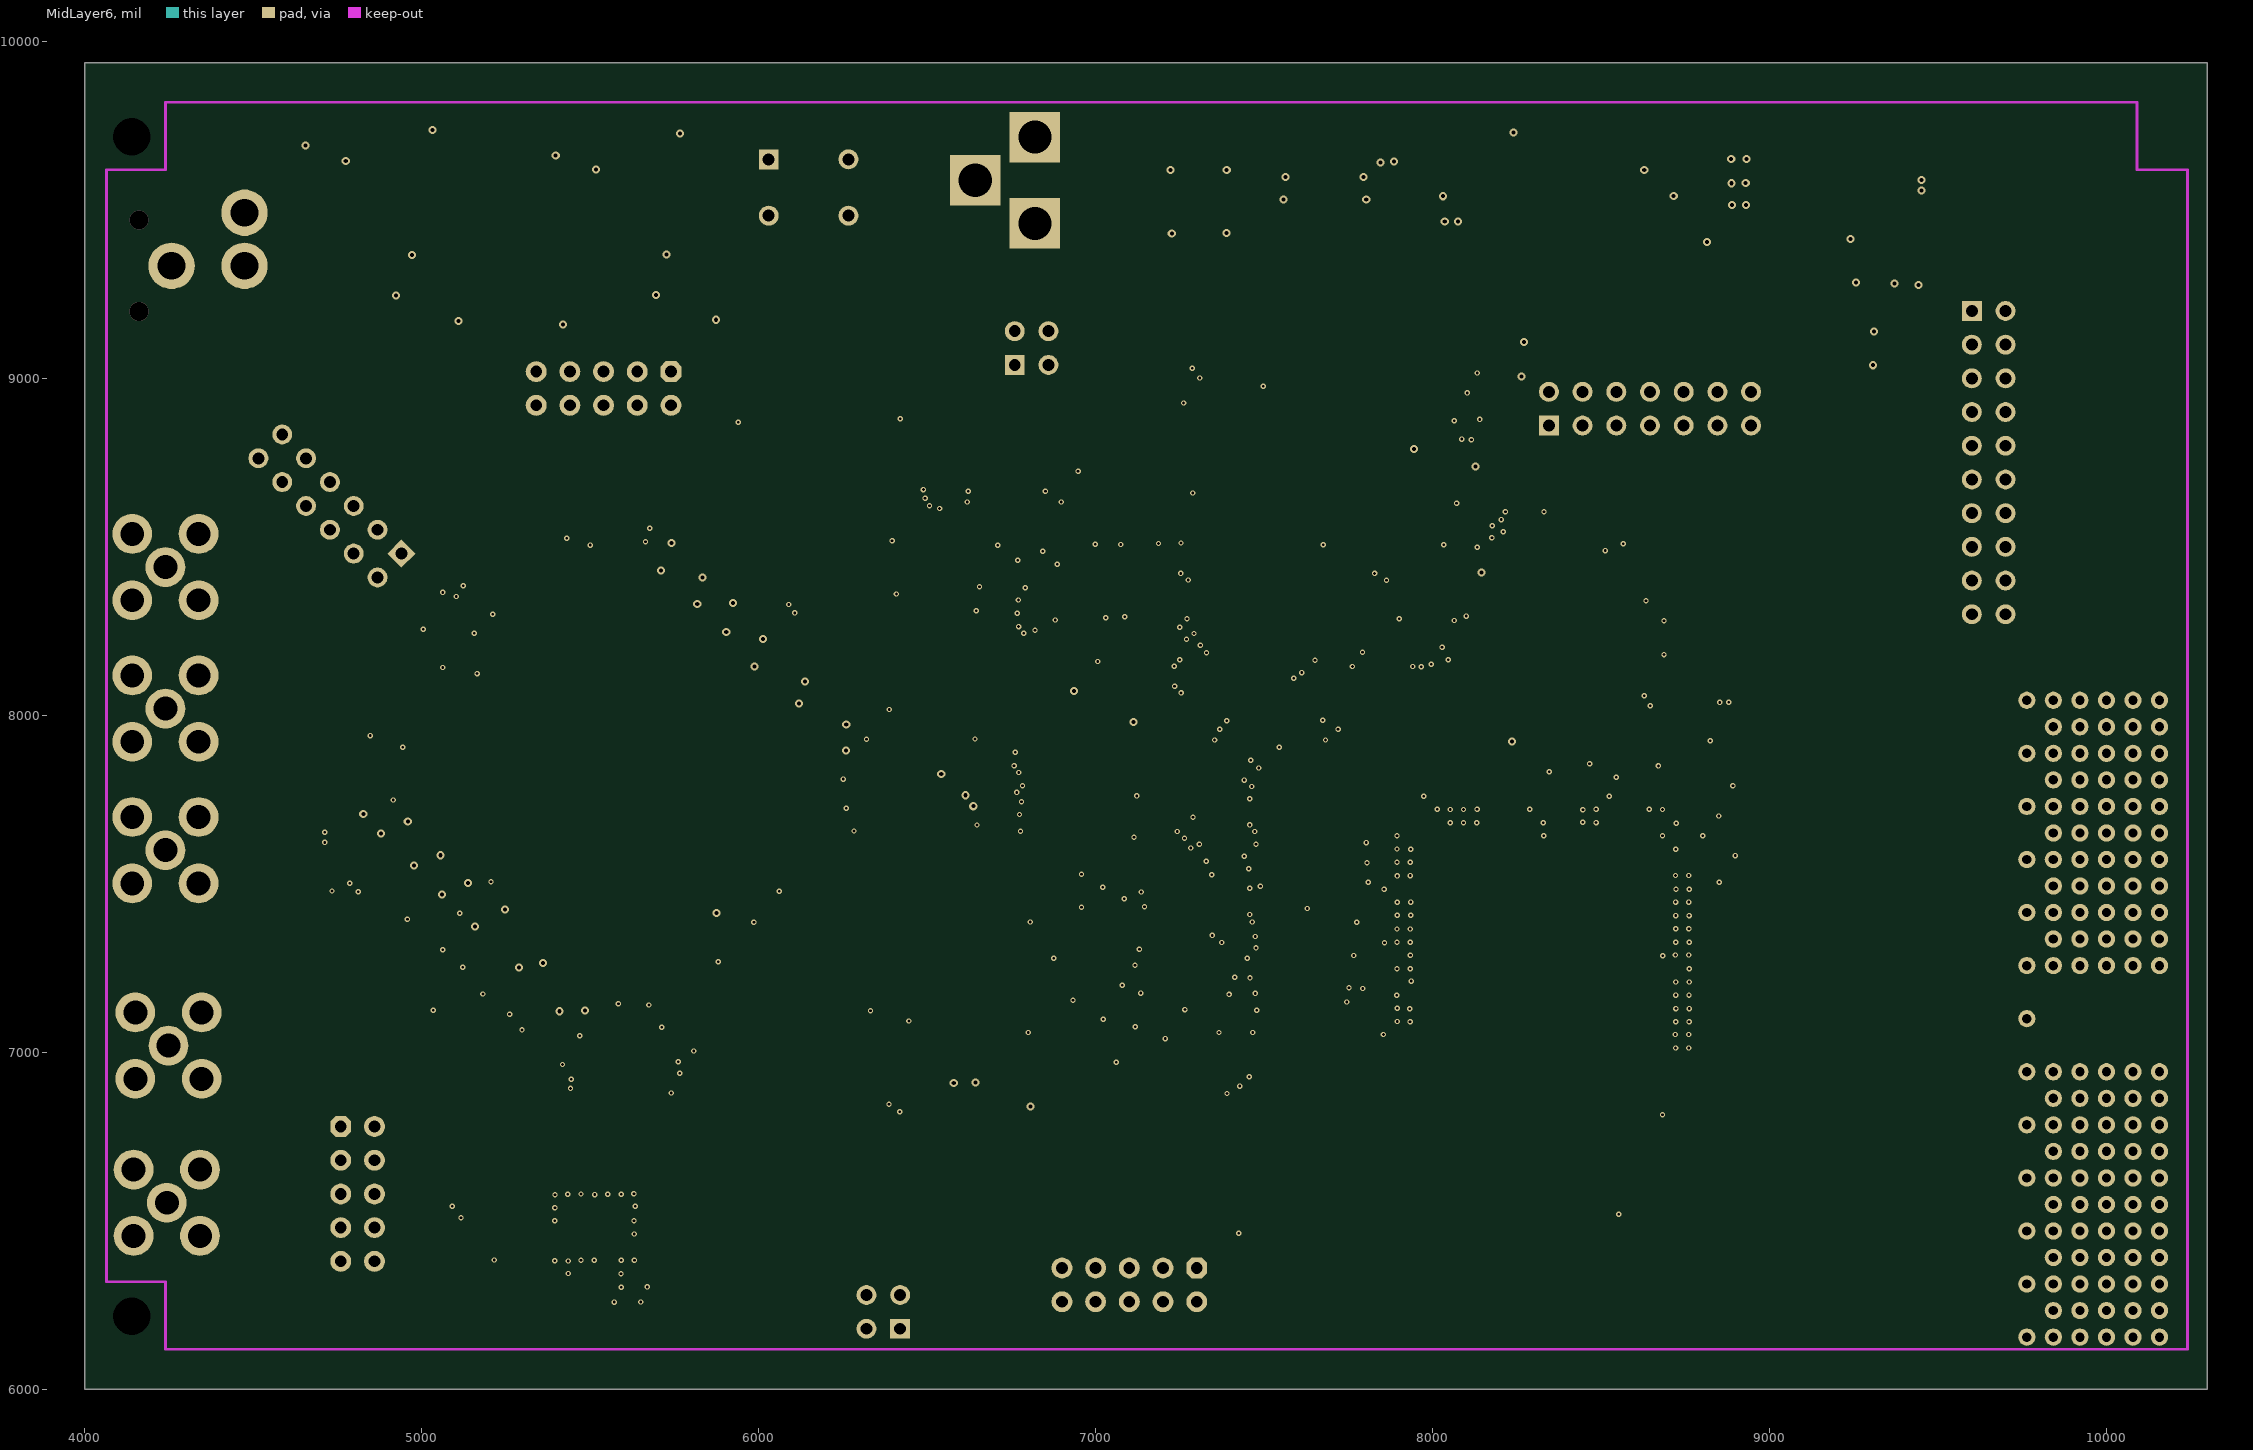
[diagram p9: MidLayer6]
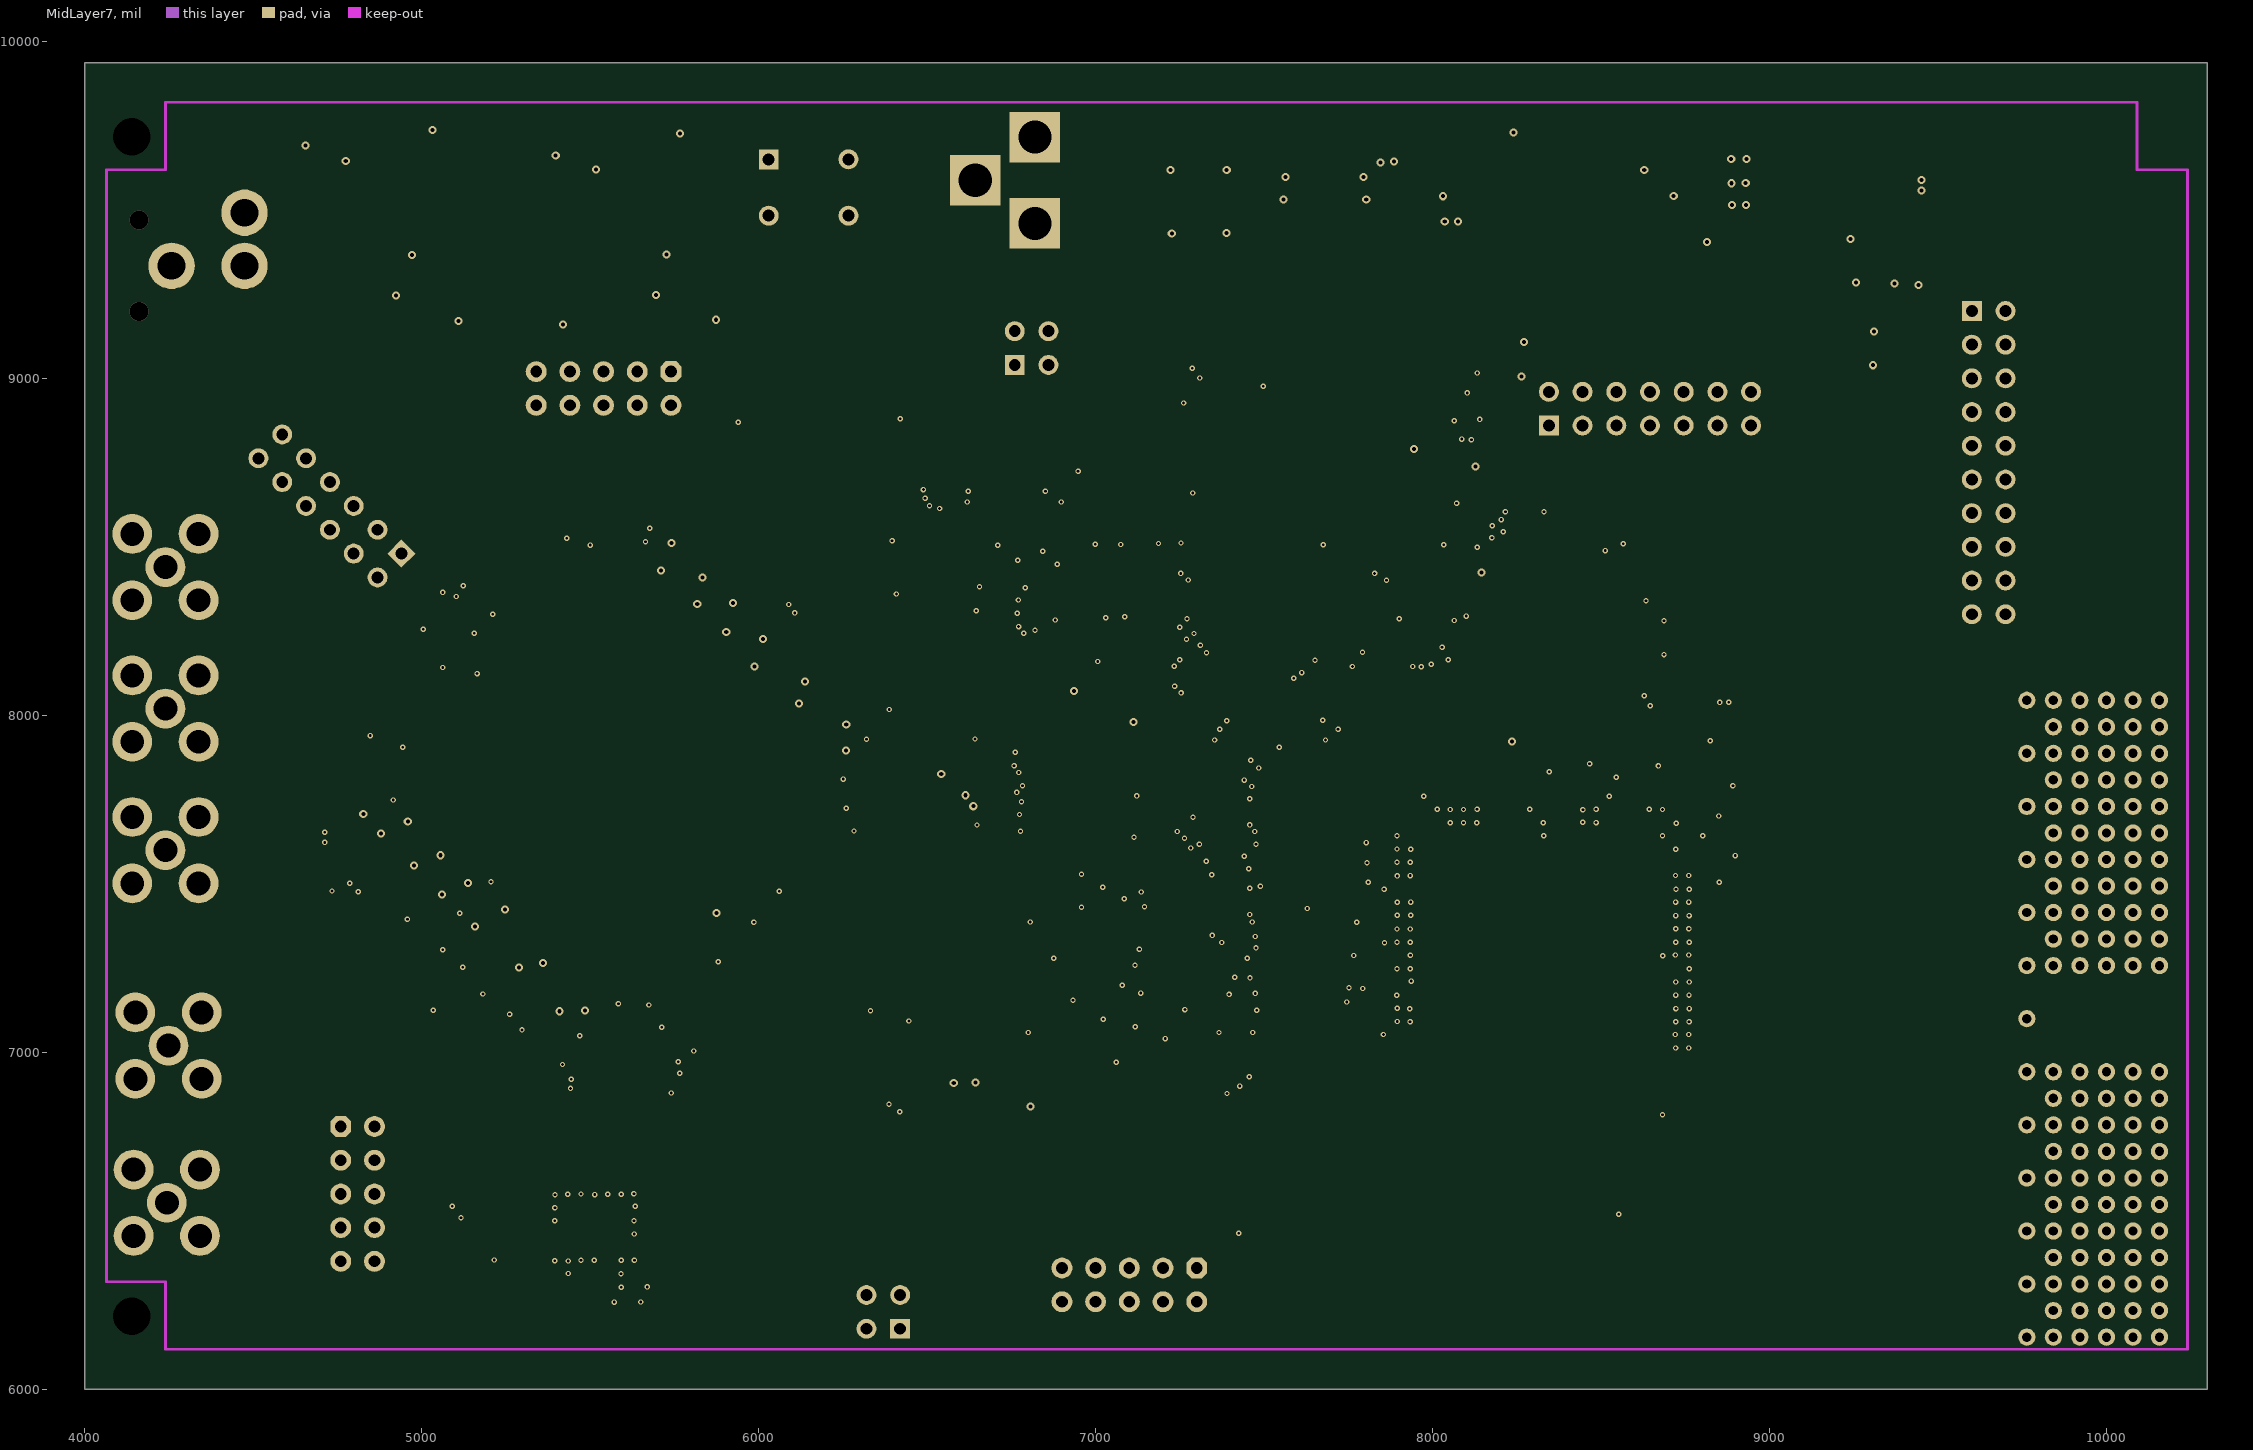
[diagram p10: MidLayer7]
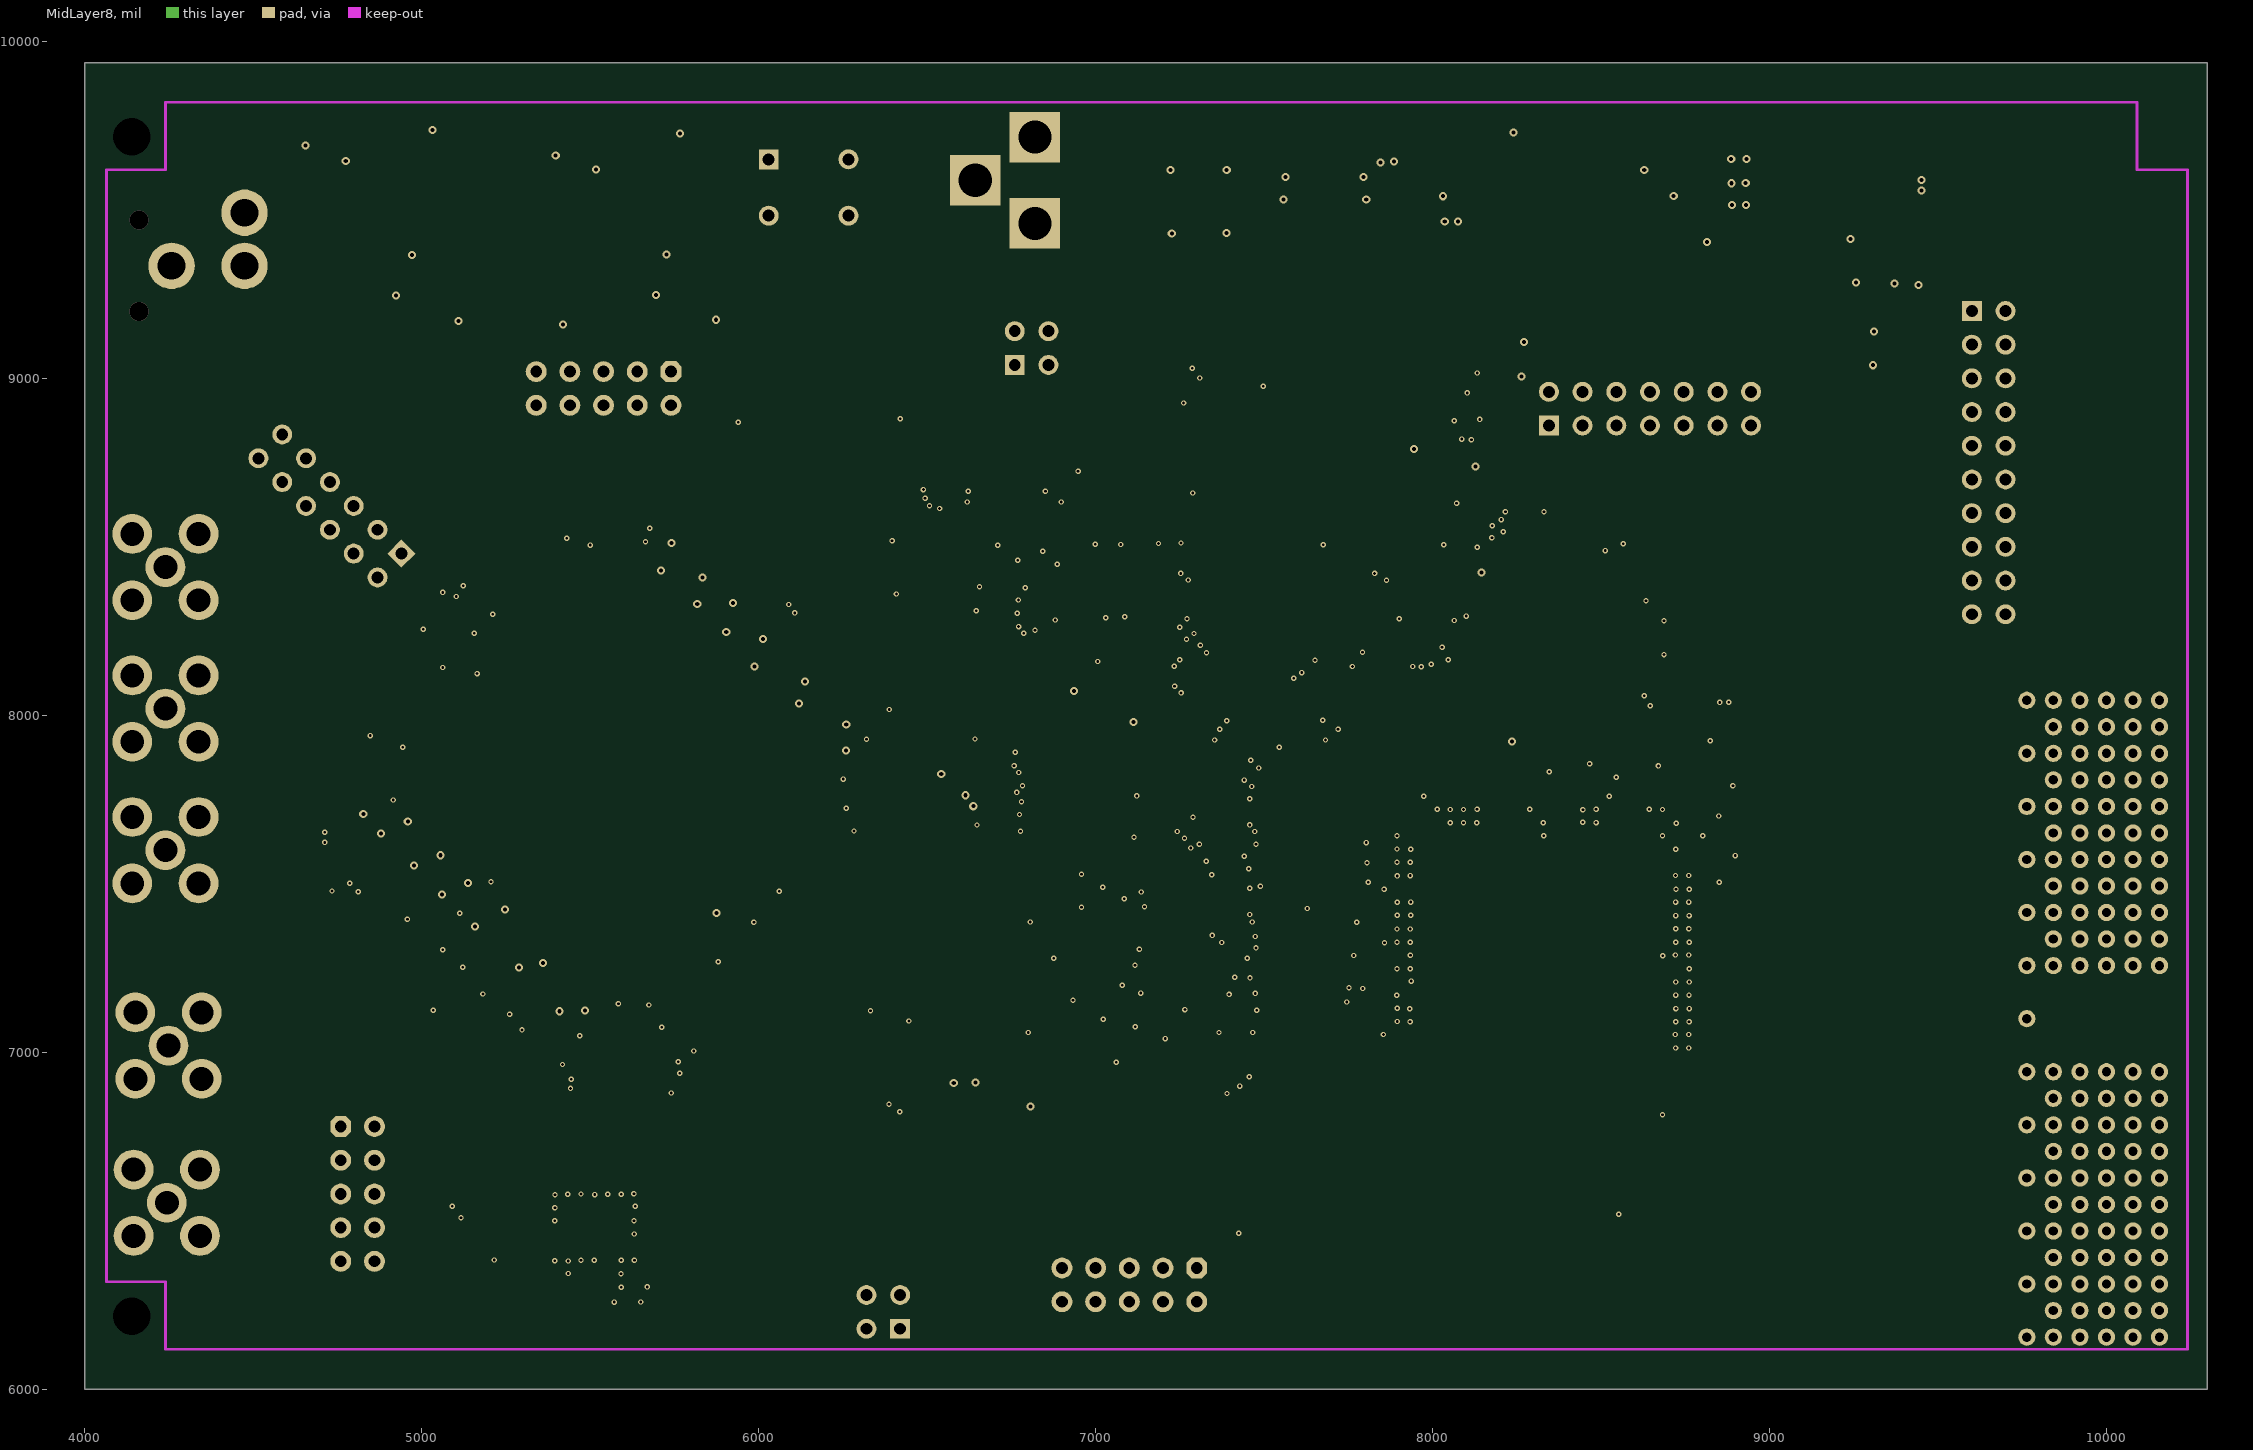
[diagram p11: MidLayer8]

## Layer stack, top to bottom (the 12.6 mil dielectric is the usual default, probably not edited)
TopLayer: signal copper 1.4
Dielectric: core 12.6, FR-4, Dk 4.8
VCC: plane copper 1.4
Dielectric: prepreg 12.6, FR-4, Dk 4.8
GROUND: plane copper 1.4, net GND
Dielectric: core 12.6, FR-4, Dk 4.8
MidLayer1: signal copper 1.4
Dielectric: prepreg 12.6, FR-4, Dk 4.8
MidLayer2: signal copper 1.4
Dielectric: core 12.6, FR-4, Dk 4.8
MidLayer3: signal copper 1.4
Dielectric: prepreg 12.6, FR-4, Dk 4.8
MidLayer4: signal copper 1.4
Dielectric: core 12.6, FR-4, Dk 4.8
MidLayer5: signal copper 1.4
Dielectric: prepreg 12.6, FR-4, Dk 4.8
MidLayer6: signal copper 1.4
Dielectric: core 12.6, FR-4, Dk 4.8
MidLayer7: signal copper 1.4
Dielectric: prepreg 12.6, FR-4, Dk 4.8
MidLayer8: signal copper 1.4
Dielectric: core 12.6, FR-4, Dk 4.8
BottomLayer: signal copper 1.4

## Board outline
4000,6000 10299,6000 10299,9937 4000,9937

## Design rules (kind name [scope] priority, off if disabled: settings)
Clearance [All] p1: gap=6
ComponentClearance ComponentClearance_1 [All] p1: gap=10 collisioncheckmode=0
HoleSize HoleSize_1 [All] p1: absolutevalues=TRUE maxlimit=100 minlimit=1 maxpercent=80.000 minpercent=20.000
LayerPairs LayerPairs_1 [All] p1: enforce=TRUE
PasteMaskExpansion PasteMaskExpansion_1 [All] p1: expansion=0
PlaneClearance PlaneClearance_1 [All] p1: clearance=10
PlaneConnect [All] p1: planeconnectstyle=Relief reliefexpansion=20 reliefentries=4 reliefconductorwidth=10 reliefairgap=10
PolygonConnect PolygonConnect_1 [All] p1: connectstyle=Relief reliefconductorwidth=10 reliefentries=4 polygonreliefangle="90 Angle"
RoutingLayers [All] p1: top layer=Horizontal mid layer 1="Not Used" mid layer 2="Not Used" mid layer 3="Not Used" mid layer 4="Not Used" mid layer 5="Not Used" mid layer 6="Not Used" mid layer 7="Not Used" mid layer 8="Not Used" bottom layer=Vertical
RoutingPriority RoutingPriority_1 [All] p1: routingpriority=0
RoutingTopology RoutingTopology_1 [All] p1: topology=Shortest
RoutingVias [All] p1: holewidth=8 width=16 viastyle="Through Hole" minholewidth=8 minwidth=16 maxholewidth=28 maxwidth=50
ShortCircuit ShortCircuit_1 [All] p1: allowed=FALSE
SolderMaskExpansion SolderMaskExpansion_1 [All] p1: expansion=2
TestPointUsage TestPointUsage_1 [All] p1: valid=0 allowmultiple=FALSE
Testpoint Testpoint_1 [All] p1: side=7 testpointundercomponent=TRUE minsize=40 maxsize=100 preferedsize=60 minholesize=20 maxholesize=40 preferedholesize=32 testpointgrid=1 style=1001 order=-539222988
UnRoutedNet UnRoutedNet_1 [All] p1:
Width [All] p1: maxlimit=40 minlimit=6 preferedwidth=6
7 further rules are at their usual default settings.

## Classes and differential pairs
component class U_Sheet4_DSP2_videoport: C133 C153 C154 C155 C156 C157 C158 C159 C160 C161 C162 C163 C164 C165 DS9 FB3 J4 R39 R40 R41 R71 R74 R76 R78 R79 R80 R81 R82 R83 R84 R86 R87 R88 R? S2 U1 U18 U19 U20 U21 U22 U23
component class U_Sheet3_power_clock: C37 C38 C39 C40 C41 C42 C43 C44 C45 C46 C47 C48 C49 C50 C51 C52 C53 C54 C55 C56 C57 C58 C59 C60 C61 C62 C63 C64 C65 C66 C67 C68 C69 C70 C71 C72 C73 C74 C75 C76 C77 C78 C79 C80 C81 C82 C83 C84 C85 C86 C87 C88 C89 C90 C91 C92 C93 C94 C95 C96 C97 C98 C99 C100 C101 C102 C103 C104 C105 C106 C107 C108 C109 C110 C111 C112 C113 C114 C115 C116 C117 C118 C119 C120 C121 C122 C123 C124 C125 C126 C127 C128 C129 C130 C131 C132 C134 C135 C136 C137 C138 C139 C140 C141 C142 C143 C144 C145 C146 C147 C148 C149 C150 C151 C152 DS6 DS7 FB1 FB2 J3 L1 Q1 R62 R63 R64 R65 R66 R67 R68 R69 R70 R72 R73 U14 U15 U16 U17
component class U_Sheet2_PXI: C32 C36 C166 J2 JP6 R60 R61 U9 U10 U11
component class U_Sheet2_DSP_EMIF: C19 C20 C21 C22 C23 C24 C25 C26 J1 R30 R31 R32 R33 R34 R35 R36 R37 R38 R47 R48 R49 R50 R51 R52 R54 R55 R56 R57 R58 R59 S1 U7 U8
component class U_Sheet1_FPGA2: C1 C2 C3 C4 C5 C6 C7 C8 C9 C10 C11 C12 C13 C14 C15 C16 C17 C18 C27 C28 C29 C30 DS1 DS2 DS3 DS4 DS5 JP1 JP2 JP3 JP4 JP5 JP7 JP8 JP9 JP10 JP11 L2 R1 R2 R3 R4 R5 R6 R7 R8 R9 R10 R11 R12 R13 R14 R15 R16 R17 R18 R19 R20 R21 R22 R23 R24 R25 R26 R27 R28 R29 R42 R43 R44 R45 R46 R53 R77 U2 U3 U4 U5 U6

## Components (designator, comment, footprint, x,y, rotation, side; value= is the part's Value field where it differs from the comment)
C1 "Cap" C1608-0603 4520,6640 r180 top
C2 "Cap" C1608-0603 4520,6540 r180 top
C3 "Cap" C1608-0603 4520,7000 r180 top
C4 "Cap" C1608-0603 4520,6900 r180 top
C5 "Cap" C1608-0603 16310.84,9082.14 r0 top
C6 "Cap" C1608-0603 19215.5,9082.14 r0 top
C7 "Cap" C1608-0603 11086.17,9082.14 r0 top
C8 "Cap" C1608-0603 16776.41,9082.14 r0 top
C9 "Cap" C1608-0603 11030.07,7536.79 r0 top
C10 "Cap" C1608-0603 10809.58,7536.79 r0 top
C11 "Cap" C1608-0603 20098.42,9097.88 r0 top
C12 "Cap" C1608-0603 9426,11233 r0 top
C13 "Cap" C1608-0603 18497.95,9097.88 r0 top
C14 "Cap" C1608-0603 16058.85,9097.88 r0 top
C15 "Cap" C1608-0603 18718.43,9097.88 r0 top
C16 "Cap" C1608-0603 10834.19,9097.88 r0 top
C17 "Cap" C1608-0603 19878.92,9097.88 r0 top
C18 "Cap" C1608-0603 12972.55,6156.45 r90 top
C19 "Cap" C1608-0603 8220,9060 r270 top
C20 "Cap" C1608-0603 6580,8360 r0 top
C21 "Cap" C1608-0603 6580,7860 r270 bottom
C22 "Cap" C1608-0603 6600,7660 r90 bottom
C23 "Cap" C1608-0603 7220,8580 r180 bottom
C24 "Cap" C1608-0603 7040,8580 r0 bottom
C25 "Cap" C1608-0603 7080,8100 r90 top
C26 "Cap" C1608-0603 6940,7980 r0 top
C27 "Cap" C1608-0603 6060,6260 r180 bottom
C28 "Cap" C1608-0603 6060,6160 r180 bottom
C29 "Cap" C1608-0603 6187,6480 r0 bottom
C30 "Cap" C1608-0603 6185,6383 r0 bottom
C32 "Cap" C1608-0603 15229.09,11172.79 r90 top
C36 "Cap" C1608-0603 11760,8640 r90 top
C37 "Cap" 0603 5457.34,11687.94 r90 top
C38 "Cap" 0603 4074.4,11687.94 r90 top
C39 "Cap" 0603 19311.44,6940.94 r90 top
C40 "Cap" 0603 17928.5,6940.94 r90 top
C41 "Cap" 0603 16566.23,6940.94 r90 top
C42 "Cap" 0603 13272.76,6940.94 r90 top
C43 "Cap" 0603 20557.11,9846.94 r90 top
C44 "Cap" 0603 17933.95,9846.94 r90 top
C45 "Cap" 0603 5687.67,11687.94 r90 top
C46 "Cap" 0603 4304.73,11687.94 r90 top
C47 "Cap" 0603 19541.77,6940.94 r90 top
C48 "Cap" 0603 18158.83,6940.94 r90 top
C49 "Cap" 0603 16776.87,6940.94 r90 top
C50 "Cap" 0603 13503.09,6940.94 r90 top
C51 "Cap" 0603 20787.43,9846.94 r90 top
C52 "Cap" 0603 18164.27,9846.94 r90 top
C53 "Cap" 0603 14679.85,9846.94 r90 top
C54 "Cap" C1608-0603 9220,9239 r180 bottom
C55 "Cap" 0603 5917.99,11687.94 r90 top
C56 "Cap" 0603 4535.05,11687.94 r90 top
C57 "Cap" 0603 3153.1,11687.94 r90 top
C58 "Cap" 0603 18389.15,6940.94 r90 top
C59 "Cap" 0603 17007.2,6940.94 r90 top
C60 "Cap" 0603 13733.42,6940.94 r90 top
C61 "Cap" 0603 20998.07,9846.94 r90 top
C62 "Cap" 0603 18394.6,9846.94 r90 top
C63 "Cap" 0603 14910.18,9846.94 r90 top
C64 "Cap" C1608-0603 9220,9339 r180 bottom
C65 "Cap" 0603 6148.32,11687.94 r90 top
C66 "Cap" 0603 4765.38,11687.94 r90 top
C67 "Cap" 0603 3383.42,11687.94 r90 top
C68 "Cap" 0603 18619.48,6940.94 r90 top
C69 "Cap" 0603 17237.52,6940.94 r90 top
C70 "Cap" 0603 13963.74,6940.94 r90 top
C71 "Cap" 0603 21208.71,9846.94 r90 top
C72 "Cap" 0603 18624.92,9846.94 r90 top
C73 "Cap" 0603 6378.65,11687.94 r90 top
C74 "Cap" 0603 4996.69,11687.94 r90 top
C75 "Cap" 0603 3613.75,11687.94 r90 top
C76 "Cap" 0603 18849.81,6940.94 r90 top
C77 "Cap" 0603 17467.85,6940.94 r90 top
C78 "Cap" 0603 15140.5,9846.94 r90 top
C79 "Cap" 0603 14194.07,6940.94 r90 top
C80 "Cap" 0603 21418.37,9846.94 r90 top
C81 "Cap" 0603 18855.25,9846.94 r90 top
C82 "Cap" 0603 6608.97,11687.94 r90 top
C83 "Cap" 0603 5227.02,11687.94 r90 top
C84 "Cap" 0603 3844.07,11687.94 r90 top
C85 "Cap" 0603 19081.12,6940.94 r90 top
C86 "Cap" 0603 17698.18,6940.94 r90 top
C87 "Cap" 0603 14424.39,6940.94 r90 top
C88 "Cap" 0603 21649.68,9846.94 r90 top
C89 "Cap" 0603 19065.89,9846.94 r90 top
C90 "Cap" 0603 15370.83,9846.94 r90 top
C91 "Cap" 0603 19296.22,9846.94 r90 top
C92 "Cap" 0603 15602.14,9846.94 r90 top
C93 "Cap" 0603 19506.86,9846.94 r90 top
C94 "Cap" 0603 15832.47,9846.94 r90 top
C95 "Cap" C1608-0603 7984,9507 r270 bottom
C96 "Cap" C1608-0603 5518,9527 r270 top
C97 "Cap" 0603 5456.16,8503.84 r315 bottom
C98 "Cap" 0603 4860,7740 r45 bottom
C99 "Cap" 0603 5136.16,7436.16 r45 bottom
C100 "Cap" 0603 4900,7680 r45 bottom
C101 "Cap" 0603 5903.84,8303.84 r225 bottom
C102 "Cap" C1608-0603 8680,9579 r90 top
C103 "Cap" 0603 5120,8160 r46 bottom
C104 "Cap" 0603 5683.84,7096.16 r135 bottom
C105 "Cap" 0603 5516.16,7076.16 r45 bottom
C106 "Cap" 0603 5000,7580 r45 bottom
C107 "Cap" 0603 6240,7940 r225 bottom
C108 "Cap" 0603 4876.16,7923.84 r315 bottom
C109 "Cap" 0603 6260,7680 r135 bottom
C110 "Cap" 0603 6320,7880 r225 bottom
C111 "Cap" 0603 5080,7500 r45 bottom
C112 "Cap" 0603 5803.84,8383.84 r225 bottom
C113 "Cap" C1608-0603 9040,9219 r90 bottom
C114 "Cap" 0603 6080,8360 r45 bottom
C115 "Cap" 0603 5880,7320 r45 bottom
C116 "Cap" 0603 5180,7402 r45 bottom
C117 "Cap" 0603 6100,8080 r225 bottom
C118 "Cap" C1608-0603 8940,9219 r90 bottom
C119 "Cap" 0603 5640,8560 r225 bottom
C120 "Cap" 0603 5440,7140 r45 bottom
C121 "Cap" 0603 5983.84,8203.84 r225 bottom
C122 "Cap" C1608-0603 8720,9099 r180 bottom
C123 "Cap" 0603 5316.16,7276.16 r45 bottom
C124 "Cap" 0603 5703.84,8483.84 r225 bottom
C125 "Cap" C1608-0603 5818,9367 r0 top
C126 "Cap" C1608-0603 8052.48,13113.76 r90 top
C127 "Cap" C1608-0603 4775,9546 r270 top
C128 "Cap" C1608-0603 5740,7600 r225 bottom
C129 "Cap" C1608-0603 5300,8040 r225 bottom
C130 "Cap" C1608-0603 5860,7480 r225 bottom
C131 "Cap" C1608-0603 5240,8100 r225 bottom
C132 "Cap" C1608-0603 5075,9366 r0 top
C133 "Cap" C1608-0603 9431.48,13113.76 r90 top
C134 "Cap Pol1" CC6032 9400,9579 r270 bottom
C135 "Cap Pol1" CC3216-1206 7864,9527 r90 bottom
C136 "Cap Pol1" CC3216-1206 5398,9547 r90 top
C137 "Cap Pol1" CC3216-1206 5818,9247 r180 top
C138 "Cap Pol1" CC6032 7360,10800 r90 top
C139 "Cap Pol1" CC3216-1206 4655,9566 r90 top
C140 "Cap Pol1" CC6032 6920,10540 r90 top
C141 "Cap Pol1" C1608-0603 5800,7540 r45 bottom
C142 "Cap Pol1" C1608-0603 5360,7980 r45 bottom
C143 "Cap Pol1" CC3216-1206 5055,9246 r180 top
C144 "Cap Pol2" CC3216-1206 15480.55,6937.98 r90 top
C145 "Cap Pol2" CC3216-1206 10600,9480 r90 top
C146 "Cap Pol2" CC3216-1206 9240,9519 r270 bottom
C147 "Cap Pol2" CC3216-1206 15761.07,6937.98 r90 top
C148 "Cap Pol2" CC3216-1206 10629.46,9843.98 r90 top
C149 "Cap Pol2" CC3216-1206 10909.98,9843.98 r90 top
C150 "Cap Pol2" CC3216-1206 16040.61,6937.98 r90 top
C151 "Cap Pol2" CC3216-1206 11240.71,9876.47 r0 top
C152 "Cap Pol2" CC3216-1206 16321.14,6937.98 r90 top
C153 "Cap" C1608-0603 14933.8,10629.46 r90 top
C154 "Cap" C1608-0603 12503.56,10629.46 r90 top
C155 "Cap" C1608-0603 15214.33,10629.46 r90 top
C156 "Cap" C1608-0603 12784.09,10629.46 r90 top
C157 "Cap" C1608-0603 15493.87,10629.46 r90 top
C158 "Cap" C1608-0603 13063.63,10629.46 r90 top
C159 "Cap" C1608-0603 15774.39,10629.46 r90 top
C160 "Cap" C1608-0603 8920,6180 r180 bottom
C161 "Cap" C1608-0603 8920,6280 r180 bottom
C162 "Cap" C1608-0603 18678.08,10629.46 r90 top
C163 "Cap" C1608-0603 8360,6620 r0 bottom
C164 "Cap Pol2" CC3216-1206 8340,6500 r180 bottom
C165 "Cap" C1608-0603 8260,7960 r180 bottom
C166 "Cap" C1608-0603 10335,6231 r90 top
DS1 "LED2" DSO-F2/D6.1 14322.55,9007.33 r90 top
DS2 "LED2" DSO-F2/D6.1 14532.21,9007.33 r90 top
DS3 "LED2" DSO-F2/D6.1 14762.53,9007.33 r90 top
DS4 "LED2" DSO-F2/D6.1 14991.87,9007.33 r90 top
DS5 "LED2" DSO-F2/D6.1 15222.2,9007.33 r90 top
DS6 "LED3" "SMD _LED" 11312.56,9088.04 r0 top
DS7 "LED3" "SMD _LED" 11542.89,9088.04 r0 top
DS9 "LED3" "SMD _LED" 8254,8424 r0 bottom
FB1 "FB" C1608-0603 5680,7660 r225 bottom
FB2 "FB" C1608-0603 5420,7920 r225 bottom
FB3 "BLM18PG121SN1" C1608-0603 8920,6380 r180 bottom
J1 "Header 7X2 JTAG" HDR2X7 8345,8860 r0 top
J2 "352495-1" PCI2-H123 9960,7099.96 r270 bottom
J3 "PWP_CON" POWER_CON 6820,9460 r90 top
J4 "RCA" RCA 4300,9380 r0 top
JP1 "Header 2" SMA 4240,7600 r0 top
JP2 "Header 2" SMA 4240,8020 r0 top
JP3 "101_JTAG" HDR2X5 4760,6780 r270 top
JP4 "JTAG" HDR2X5 5740,9020 r180 top
JP5 "AS mode" HDR2X5 7300,6360 r180 top
JP6 "Header 10X2" HDR2X10 9600,9200 r270 top
JP7 "Header 2" SMA 4240,8440 r0 top
JP8 "Header 2" SMA 4244,6554 r0 top
JP9 "Header 2" SMA 4249,7020 r0 top
JP10 "Header 6X2" HDR2X6 4940,8480 r135 top
JP11 "Header 2X2" HDR2X2 6420,6180 r90 top
L1 "Inductor Iron" L44.7uH 8500,9619 r270 bottom
Q1 "QNPN3904" "SO-G3 for NPN" 8100,9640 r180 bottom
R1 "Res2" C1608-0603 4720,8880 r315 top
R2 "Res2" C1608-0603 4860,8940 r45 top
R3 "Res2" C1608-0603 4800,9000 r45 top
R4 "Res2" C1608-0603 4860,8740 r315 top
R5 "Res2" C1608-0603 5000,8800 r45 top
R6 "Res2" C1608-0603 4940,8860 r45 top
R7 "Res2" C1608-0603 5000,8580 r315 top
R8 "Res2" C1608-0603 6200,6580 r0 bottom
R9 "Res2" C1608-0603 5160,8660 r45 top
R10 "Res2" C1608-0603 5100,8720 r45 top
R11 "Res2" C1608-0603 11229.88,7536.79 r0 top
R12 "Res2" C1608-0603 5199,6667 r90 top
R13 "Res2" C1608-0603 5099,6667 r90 top
R14 "Res2" C1608-0603 5320,9160 r0 top
R15 "Res2" C1608-0603 11760.42,9097.88 r0 top
R16 "Res2" C1608-0603 5520,9160 r180 top
R17 "Res2" C1608-0603 5940,8960 r90 top
R18 "Res2" C1608-0603 11920.86,7536.79 r0 top
R19 "Res2" C1608-0603 12141.34,7536.79 r0 top
R20 "Res2" C1608-0603 12386.43,9062.45 r90 top
R21 "Res2" C1608-0603 12651.21,9097.88 r0 top
R22 "Res2" C1608-0603 5988,7700 r0 bottom
R23 "Res2" C1608-0603 5988,7800 r0 bottom
R24 "Res2" C1608-0603 6420,6920 r135 top
R25 "Res2" C1608-0603 3600,8140 r270 bottom
R26 "Res2" C1608-0603 7425,6380 r90 top
R27 "Res2" C1608-0603 6008,7900 r180 bottom
R28 "Res2" C1608-0603 6060,7600 r0 bottom
R29 "Res2" C1608-0603 5320,8300 r0 bottom
R30 "R0604_4" R0603_4 7580,7540 r180 bottom
R31 "R0604_4" R0603_4 7900,8040 r90 bottom
R32 "R0604_4" R0603_4 8100,8040 r90 bottom
R33 "R0604_4" R0603_4 7960,8040 r90 top
R34 "R0604_4" R0603_4 8140,8040 r90 top
R35 "R0604_4" R0603_4 7580,7520 r180 top
R36 "R0604_4" R0603_4 7580,7680 r180 top
R37 "R0604_4" R0603_4 7580,7720 r180 bottom
R38 "R0604_4" R0603_4 7580,7880 r180 bottom
R39 "Res1" CR1608-0603 17405.38,10629.46 r90 top
R40 "Res1" CR1608-0603 4720,9240 r180 top
R41 "Res1" CR1608-0603 17635.7,10629.46 r90 top
R42 "Res2" C1608-0603 4480,7960 r270 top
R43 "Res2" C1608-0603 4480,7660 r90 top
R44 "Res2" C1608-0603 4560,8520 r225 top
R45 "Res2" C1608-0603 4740,8320 r225 top
R46 "Res2" C1608-0603 4900,8280 r225 top
R47 "R0604_4" R0603_4 7580,7200 r180 top
R48 "R0604_4" R0603_4 7580,7040 r180 top
R49 "R0604_4" R0603_4 7580,7220 r180 bottom
R50 "R0604_4" R0603_4 7580,6880 r180 top
R51 "R0604_4" R0603_4 7580,7060 r180 bottom
R52 "R0604_4" R0603_4 7580,7360 r180 top
R53 "Res2" C1608-0603 6058,6423 r90 bottom
R54 "R0604_4" R0603_4 7580,7380 r180 bottom
R55 "Res1" CR1608-0603 7240,7540 r180 top
R56 "Res1" CR1608-0603 10334.17,7808.45 r90 top
R57 "Res1" CR1608-0603 10563.51,7808.45 r90 top
R58 "Res1" CR1608-0603 7960,8660 r180 top
R59 "Res1" CR1608-0603 7200,8660 r180 top
R60 "Res2" C1608-0603 12280,8700 r90 top
R61 "Res1" CR1608-0603 9526,11013 r0 top
R62 "Res2" CR1608-0603 6858,11698.76 r90 top
R63 "Res2" CR1608-0603 7088.33,11698.76 r90 top
R64 "Res1" CR1608-0603 8240,9640 r270 bottom
R65 "Res1" CR1608-0603 9220,9039 r180 bottom
R66 "Res1" CR1608-0603 9220,9139 r0 bottom
R67 "Res1" CR1608-0603 8800,9359 r180 bottom
R68 "Res1" CR1608-0603 8980,9359 r180 bottom
R69 "Res1" CR1608-0603 8540,9099 r180 bottom
R70 "Res1" CR1608-0603 8800,9239 r180 bottom
R71 "Res1" CR1608-0603 6280,8960 r180 bottom
R72 "Res3" CR1608-0603 8200,9480 r0 bottom
R73 "Res3" CR1608-0603 7980,9680 r270 bottom
R74 "Res1" CR1608-0603 10894.23,10629.46 r90 top
R76 "Res1" CR1608-0603 8580,7980 r270 bottom
R77 "Res2" C1608-0603 4480,8360 r270 top
R78 "Res1" CR1608-0603 9060,8240 r90 top
R79 "Res1" CR1608-0603 8720,8240 r0 bottom
R80 "Res1" CR1608-0603 8640,6520 r180 top
R81 "Res1" CR1608-0603 6280,8660 r0 bottom
R82 "Res1" CR1608-0603 8760,6600 r90 bottom
R83 "Res1" CR1608-0603 8720,8340 r0 bottom
R84 "Res1" CR1608-0603 8720,8140 r0 bottom
R86 "Res1" CR1608-0603 8580,8180 r90 bottom
R87 "Res1" CR1608-0603 9100,8580 r180 bottom
R88 "Res1" CR1608-0603 9120,8480 r180 bottom
S1 "SW DIP-2" HEADER2X2 6760,9040 r0 top
S2 "SW-PB" BUTTON 6180,9600 r270 top
U1 "TMS320DM642" GNZ548 8820,7780 r0 bottom
U2 "EP1C12Q240C6" PQFP240 5579,7807 r135 top
U3 "CYP15G0101" BGA100x10 5690,6284 r180 top
U4 "Oscillator   27MHz" OSC 6720,6780 r270 top
U5 "EPCS1SI8" SOIC8 7140,6620 r0 top
U6 "Oscillator   20MHz" OSC 3720,8460 r0 bottom
U7 "Am29LV800B" TSOP48 7400,8760 r0 bottom
U8 "HY57V283220" TSOP86 7180,8480 r180 bottom
U9 "SN74CBT16210" SSOP48 9380,6940 r180 top
U10 "SN74CBT16210" SSOP48 9380,7460 r180 top
U11 "SN74CBT16210" SSOP48 9380,7480 r180 bottom
U14 "TPS75733" SOT23-5S 7682,9665 r180 bottom
U15 "TPS54310" PWP20 8780,9439 r0 bottom
U16 "AS1117-1.5V" LM1117 5818,9747 r90 top
U17 "AS1117-2.5V" LM1117 5080,9760 r90 top
U18 "TPS3823-33" DBV5 6340,8880 r180 bottom
U19 "SAA7121H" QFP44_2 8340,8280 r45 top
U20 "ACF451832" ACF451832 8200,6360 r0 bottom
U21 "Oscillator" OSC50MHz 8760,6300 r0 bottom
U22 "93C66B" SO-G8 9160,8520 r0 top
U23 "Oscillator" OSC50MHz 8340,8080 r270 bottom

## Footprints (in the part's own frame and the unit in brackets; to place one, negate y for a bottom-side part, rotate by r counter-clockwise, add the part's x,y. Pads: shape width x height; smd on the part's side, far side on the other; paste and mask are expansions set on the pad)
0603 [mil] "for DSP"
  rect 35x30 smd: 1(0,0) 2(62.99,0)
  silkscreen extent -22,-19 84,19
ACF451832 [mm] "for ACF451832-333-T"
  rect 1.2x2.5 smd: 1(0,0) 2(2.5,0) 3(5,0)
  silkscreen extent -0.76,-1.63 5.79,1.55
BGA100x10 [mm] "for CYP15G0101"
  round 0.45 smd: A1(0,0) A2(1,0) A3(2,0) A4(3,0) A5(4,0) A6(5,0) A7(6,0) A8(7,0) A9(8,0) A10(9,0) B1(0,-1) B2(1,-1) B3(2,-1) B4(3,-1) B5(4,-1) B6(5,-1) B7(6,-1) B8(7,-1) B9(8,-1) B10(9,-1) C1(0,-2) C2(1,-2) C3(2,-2) C4(3,-2) C5(4,-2) C6(5,-2) C7(6,-2) C8(7,-2) C9(8,-2) C10(9,-2) D1(0,-3) D2(1,-3) D3(2,-3) D4(3,-3) D5(4,-3) D6(5,-3) D7(6,-3) D8(7,-3) D9(8,-3) D10(9,-3) E1(0,-4) E2(1,-4) E3(2,-4) E4(3,-4) E5(4,-4) E6(5,-4) E7(6,-4) E8(7,-4) E9(8,-4) E10(9,-4) F1(0,-5) F2(1,-5) F3(2,-5) F4(3,-5) F5(4,-5) F6(5,-5) F7(6,-5) F8(7,-5) F9(8,-5) F10(9,-5) G1(0,-6) G2(1,-6) G3(2,-6) G4(3,-6) G5(4,-6) G6(5,-6) G7(6,-6) G8(7,-6) G9(8,-6) G10(9,-6) H1(0,-7) H2(1,-7) H3(2,-7) H4(3,-7) H5(4,-7) H6(5,-7) H7(6,-7) H8(7,-7) H9(8,-7) H10(9,-7) J1(0,-8) J2(1,-8) J3(2,-8) J4(3,-8) J5(4,-8) J6(5,-8) J7(6,-8) J8(7,-8) J9(8,-8) J10(9,-8) K1(0,-9) K2(1,-9) K3(2,-9) K4(3,-9) K5(4,-9) K6(5,-9) K7(6,-9) K8(7,-9) K9(8,-9) K10(9,-9)
  silkscreen extent -1,-10 10,1
BUTTON [mm]
  rect 1.5x1.5 hole 0.9: 1(-1.27,-3.81)
  round 1.5 hole 0.9: 2(2.98,-3.81) 3(2.98,2.2) 4(-1.27,2.2)
  silkscreen extent -2.34,-4.93 4.04,3.12
C1608-0603 [mm]
  rect 1.1x1 smd: 1(-0.85,0) 2(0.85,0)
  silkscreen extent -1.8,-0.9 1.8,0.9
CC3216-1206 [mm]
  rect 1.6x1.8 smd: 1(-1.4,0) 2(1.4,0)
  silkscreen extent -2.6,-1.3 2.1,1.3
CC6032 [mm] "for 100uF"
  rect 2x3.5 smd: 1(0,0) 2(6,0)
  silkscreen extent -1.56,-2.03 7.34,2.01
CR1608-0603 [mm]
  rect 1.1x1 smd: 1(-0.85,0) 2(0.85,0)
  silkscreen extent -1.8,-0.9 1.8,0.9
DBV5 [mm] "DBV5;DBV (R-PDSO-G5);PSO;for TPS3823-33"
  rect 2x0.6 smd: 1(0,0)
  oval 2x0.6 smd: 2(0,-0.95) 3(0,-1.9) 4(3,-1.9) 5(3,0)
  silkscreen extent -1.27,-2.41 4.45,0.48
DSO-F2/D6.1 [mm]
  rect 1.5x1.5 smd: 1(-1.75,0) 2(1.75,0)
  silkscreen extent -2.9,-1.15 3.2,1.15
GNZ548 [mm] "BGA;548 Balls;Body 27 x 27 mm;for DM642"
  round 0.47 smd: A1(0,0) A2(-1,0) A3(-2,0) A4(-3,0) A5(-4,0) A6(-5,0) A7(-6,0) A8(-7,0) A9(-8,0) A10(-9,0) A11(-10,0) A12(-11,0) A13(-12,0) A14(-13,0) A15(-14,0) A16(-15,0) A17(-16,0) A18(-17,0) A19(-18,0) A20(-19,0) A21(-20,0) A22(-21,0) A23(-22,0) A24(-23,0) A25(-24,0) A26(-25,0) AA1(0,20) AA2(-1,20) AA3(-2,20) AA4(-3,20) AA5(-4,20) AA6(-5,20) AA7(-6,20) AA8(-7,20) AA9(-8,20) AA10(-9,20) AA11(-10,20) AA12(-11,20) AA13(-12,20) AA14(-13,20) AA15(-14,20) AA16(-15,20) AA17(-16,20) AA18(-17,20) AA19(-18,20) AA20(-19,20) AA21(-20,20) AA22(-21,20) AA23(-22,20) AA24(-23,20) AA25(-24,20) AA26(-25,20) AB1(0,21) AB2(-1,21) AB3(-2,21) AB4(-3,21) AB5(-4,21) AB6(-5,21) AB7(-6,21) AB8(-7,21) AB9(-8,21) AB10(-9,21) AB11(-10,21) AB12(-11,21) AB13(-12,21) AB14(-13,21) AB15(-14,21) AB16(-15,21) AB17(-16,21) AB18(-17,21) AB19(-18,21) AB20(-19,21) AB21(-20,21) AB22(-21,21) AB23(-22,21) AB24(-23,21) AB25(-24,21) AB26(-25,21) AC1(0,22) AC2(-1,22) AC3(-2,22) AC4(-3,22) AC5(-4,22) AC6(-5,22) AC7(-6,22) AC8(-7,22) AC9(-8,22) AC10(-9,22) AC11(-10,22) AC12(-11,22) AC13(-12,22) AC14(-13,22) AC15(-14,22) AC16(-15,22) AC17(-16,22) AC18(-17,22) AC19(-18,22) AC20(-19,22) AC21(-20,22) AC22(-21,22) AC23(-22,22) AC24(-23,22) AC25(-24,22) AC26(-25,22) AD1(0,23) AD2(-1,23) AD3(-2,23) AD4(-3,23) AD5(-4,23) AD6(-5,23) AD7(-6,23) AD8(-7,23) AD9(-8,23) AD10(-9,23) AD11(-10,23) AD12(-11,23) AD13(-12,23) AD14(-13,23) AD15(-14,23) AD16(-15,23) AD17(-16,23) AD18(-17,23) AD19(-18,23) AD20(-19,23) AD21(-20,23) AD22(-21,23) AD23(-22,23) AD24(-23,23) AD25(-24,23) AD26(-25,23) AE1(0,24) AE2(-1,24) AE3(-2,24) AE4(-3,24) AE5(-4,24) AE6(-5,24) AE7(-6,24) AE8(-7,24) AE9(-8,24) AE10(-9,24) AE11(-10,24) AE12(-11,24) AE13(-12,24) AE14(-13,24) AE15(-14,24) AE16(-15,24) AE17(-16,24) AE18(-17,24) AE19(-18,24) AE20(-19,24) AE21(-20,24) AE22(-21,24) AE23(-22,24) AE24(-23,24) AE25(-24,24) AE26(-25,24) AF1(0,25) AF2(-1,25) AF3(-2,25) AF4(-3,25) AF5(-4,25) AF6(-5,25) AF7(-6,25) AF8(-7,25) AF9(-8,25) AF10(-9,25) AF11(-10,25) AF12(-11,25) AF13(-12,25) AF14(-13,25) AF15(-14,25) AF16(-15,25) AF17(-16,25) AF18(-17,25) AF19(-18,25) AF20(-19,25) AF21(-20,25) AF22(-21,25) AF23(-22,25) AF24(-23,25) AF25(-24,25) AF26(-25,25) B1(0,1) B2(-1,1) B3(-2,1) B4(-3,1) B5(-4,1) B6(-5,1) B7(-6,1) B8(-7,1) B9(-8,1) B10(-9,1) B11(-10,1) B12(-11,1) B13(-12,1) B14(-13,1) B15(-14,1) B16(-15,1) B17(-16,1) B18(-17,1) B19(-18,1) B20(-19,1) B21(-20,1) B22(-21,1) B23(-22,1) B24(-23,1) B25(-24,1) B26(-25,1) C1(0,2) C2(-1,2) C3(-2,2) C4(-3,2) C5(-4,2) C6(-5,2) C7(-6,2) C8(-7,2) C9(-8,2) C10(-9,2) C11(-10,2) C12(-11,2) C13(-12,2) C14(-13,2) C15(-14,2) C16(-15,2) C17(-16,2) C18(-17,2) C19(-18,2) C20(-19,2) C21(-20,2) C22(-21,2) C23(-22,2) C24(-23,2) C25(-24,2) C26(-25,2) D1(0,3) D2(-1,3) D3(-2,3) D4(-3,3) D5(-4,3) D6(-5,3) D7(-6,3) D8(-7,3) D9(-8,3) D10(-9,3) D11(-10,3) D12(-11,3) D13(-12,3) D14(-13,3) D15(-14,3) D16(-15,3) D17(-16,3) D18(-17,3) D19(-18,3) D20(-19,3) D21(-20,3) D22(-21,3) D23(-22,3) D24(-23,3) D25(-24,3) D26(-25,3) E1(0,4) E2(-1,4) E3(-2,4) E4(-3,4) E5(-4,4) E6(-5,4) E7(-6,4) E8(-7,4) E9(-8,4) E10(-9,4) E11(-10,4) E12(-11,4) E13(-12,4) E14(-13,4) E15(-14,4) E16(-15,4) E17(-16,4) E18(-17,4) E19(-18,4) E20(-19,4) E21(-20,4) E22(-21,4) E23(-22,4) E24(-23,4) E25(-24,4) E26(-25,4) F1(0,5) F2(-1,5) F3(-2,5) F4(-3,5) F5(-4,5) F6(-5,5) F7(-6,5) F8(-7,5) F9(-8,5) F10(-9,5) F11(-10,5) F12(-11,5) F13(-12,5) F14(-13,5) F15(-14,5) F16(-15,5) F17(-16,5) F18(-17,5) F19(-18,5) F20(-19,5) F21(-20,5) F22(-21,5) F23(-22,5) F24(-23,5) F25(-24,5) F26(-25,5) G1(0,6) G2(-1,6) G3(-2,6) G4(-3,6) G5(-4,6) G6(-5,6) G7(-6,6) G8(-7,6) G9(-8,6) G10(-9,6) G11(-10,6) G12(-11,6) G13(-12,6) G14(-13,6) G15(-14,6) G16(-15,6) G17(-16,6) G18(-17,6) G19(-18,6) G20(-19,6) G21(-20,6) G22(-21,6) G23(-22,6) G24(-23,6) G25(-24,6) G26(-25,6) H1(0,7) H2(-1,7) H3(-2,7) H4(-3,7) H5(-4,7) H6(-5,7) H7(-6,7) H20(-19,7) H21(-20,7) H22(-21,7) H23(-22,7) H24(-23,7) H25(-24,7) H26(-25,7) J1(0,8) J2(-1,8) J3(-2,8) J4(-3,8) J5(-4,8) J6(-5,8) J7(-6,8) J20(-19,8) J21(-20,8) J22(-21,8) J23(-22,8) J24(-23,8) J25(-24,8) J26(-25,8) K1(0,9) K2(-1,9) K3(-2,9) K4(-3,9) K5(-4,9) K6(-5,9) K7(-6,9) K20(-19,9) K21(-20,9) K22(-21,9) K23(-22,9) K24(-23,9) K25(-24,9) K26(-25,9) L1(0,10) L2(-1,10) L3(-2,10) L4(-3,10) L5(-4,10) L6(-5,10) L7(-6,10) L20(-19,10) L21(-20,10) L22(-21,10) L23(-22,10) L24(-23,10) L25(-24,10) L26(-25,10) M1(0,11) M2(-1,11) M3(-2,11) M4(-3,11) M5(-4,11) M6(-5,11) M7(-6,11) M12(-11,11) M13(-12,11) M14(-13,11) M15(-14,11) M20(-19,11) M21(-20,11) M22(-21,11) M23(-22,11) M24(-23,11) M25(-24,11) M26(-25,11) N1(0,12) N2(-1,12) N3(-2,12) N4(-3,12) N5(-4,12) N6(-5,12) N7(-6,12) N12(-11,12) N13(-12,12) N14(-13,12) N15(-14,12) N20(-19,12) N21(-20,12) N22(-21,12) N23(-22,12) N24(-23,12) N25(-24,12) N26(-25,12) P1(0,13) P2(-1,13) P3(-2,13) P4(-3,13) P5(-4,13) P6(-5,13) P7(-6,13) P12(-11,13) P13(-12,13) P14(-13,13) P15(-14,13) P20(-19,13) P21(-20,13) P22(-21,13) P23(-22,13) P24(-23,13) P25(-24,13) P26(-25,13) R1(0,14) R2(-1,14) R3(-2,14) R4(-3,14) R5(-4,14) R6(-5,14) R7(-6,14) R12(-11,14) R13(-12,14) R14(-13,14) R15(-14,14) R20(-19,14) R21(-20,14) R22(-21,14) R23(-22,14) R24(-23,14) R25(-24,14) R26(-25,14) T1(0,15) T2(-1,15) T3(-2,15) T4(-3,15) T5(-4,15) T6(-5,15) T7(-6,15) T20(-19,15) T21(-20,15) T22(-21,15) T23(-22,15) T24(-23,15) T25(-24,15) T26(-25,15) U1(0,16) U2(-1,16) U3(-2,16) U4(-3,16) U5(-4,16) U6(-5,16) U7(-6,16) U20(-19,16) U21(-20,16) U22(-21,16) U23(-22,16) U24(-23,16) U25(-24,16) U26(-25,16) V1(0,17) V2(-1,17) V3(-2,17) V4(-3,17) V5(-4,17) V6(-5,17) V7(-6,17) V20(-19,17) V21(-20,17) V22(-21,17) V23(-22,17) V24(-23,17) V25(-24,17) V26(-25,17) W1(0,18) W2(-1,18) W3(-2,18) W4(-3,18) W5(-4,18) W6(-5,18) W7(-6,18) W20(-19,18) W21(-20,18) W22(-21,18) W23(-22,18) W24(-23,18) W25(-24,18) W26(-25,18) Y1(0,19) Y2(-1,19) Y3(-2,19) Y4(-3,19) Y5(-4,19) Y6(-5,19) Y7(-6,19) Y8(-7,19) Y9(-8,19) Y10(-9,19) Y11(-10,19) Y12(-11,19) Y13(-12,19) Y14(-13,19) Y15(-14,19) Y16(-15,19) Y17(-16,19) Y18(-17,19) Y19(-18,19) Y20(-19,19) Y21(-20,19) Y22(-21,19) Y23(-22,19) Y24(-23,19) Y25(-24,19) Y26(-25,19)
  silkscreen extent -26,-1.02 1.8,26
HDR2X2 [mm] "Connector; Header; 2x2 Position"
  rect 1.5x1.5 hole 0.9: 1(0,0)
  round 1.5 hole 0.9: 2(0,2.54) 3(2.54,0) 4(2.54,2.54)
  silkscreen extent -1.27,-1.27 3.81,3.81
HDR2X5 [mil]
  oct 62x62 hole 35: 1(0,0)
  round 62 hole 35: 2(0,100) 3(100,0) 4(100,100) 5(200,0) 6(200,100) 7(300,0) 8(300,100) 9(400,0) 10(400,100)
  silkscreen extent -50,-50 450,150
HDR2X6 [mm] "Connector; Header; 6x2 Position"
  rect 1.5x1.5 hole 0.9: 1(0,0)
  round 1.5 hole 0.9: 2(0,2.54) 3(2.54,0) 4(2.54,2.54) 5(5.08,0) 6(5.08,2.54) 7(7.62,0) 8(7.62,2.54) 9(10.16,0) 10(10.16,2.54) 11(12.7,0) 12(12.7,2.54)
  silkscreen extent -1.27,-1.27 13.97,3.81
HDR2X7 [mm] "Connector; Header; 7x2 Position"
  rect 1.5x1.5 hole 0.9: 1(0,0)
  round 1.5 hole 0.9: 2(0,2.54) 3(2.54,0) 4(2.54,2.54) 5(5.08,0) 6(5.08,2.54) 7(7.62,0) 8(7.62,2.54) 9(10.16,0) 10(10.16,2.54) 11(12.7,0) 12(12.7,2.54) 13(15.24,0) 14(15.24,2.54)
  silkscreen extent -1.27,-1.27 16.51,3.81
HDR2X10 [mm] "Connector; Header; 10x2 Position"
  rect 1.5x1.5 hole 0.9: 1(0,0)
  round 1.5 hole 0.9: 2(0,2.54) 3(2.54,0) 4(2.54,2.54) 5(5.08,0) 6(5.08,2.54) 7(7.62,0) 8(7.62,2.54) 9(10.16,0) 10(10.16,2.54) 11(12.7,0) 12(12.7,2.54) 13(15.24,0) 14(15.24,2.54) 15(17.78,0) 16(17.78,2.54) 17(20.32,0) 18(20.32,2.54) 19(22.86,0) 20(22.86,2.54)
  silkscreen extent -1.27,-1.27 24.13,3.81
HEADER2X2 [mm]
  rect 1.5x1.5 hole 0.9: 1(0,0)
  round 1.5 hole 0.9: 2(0,2.54) 3(2.54,0) 4(2.54,2.54)
  silkscreen extent -1.27,-1.27 3.81,3.81
L44.7uH [mm] "for L4"
  rect 3.5x3.5 smd: 1(0,0) 2(10,0)
  silkscreen extent -1.78,-5 11.81,5
LM1117 [mil]
  rect 90x42 smd: 1(-250,141)
  oval 90x42 smd: 2(-250,51) 3(-250,-39)
  rect 100x130 smd: 2(-20,51)
  silkscreen extent -184,-84 -85,186
OSC [mm]
  rect 2x3 smd: 1(-5,2.134) 2(-5,-2.87) 3(0,-2.866) 4(0,2.134)
  silkscreen extent -6.22,-4.52 1.19,4.48
OSC50MHz [mm] "for 50MHz"
  rect 2x3 smd: 1(-5,2.134) 2(-5,-2.87) 3(0,-2.866) 4(0,2.134)
  silkscreen extent -6.22,-4.52 1.19,4.48
PCI2-H123 [mm]
  round 1.3 hole 0.7: A1(24,-5) A2(22,-5) A3(20,-5) A4(18,-5) A5(16,-5) A6(14,-5) A7(12,-5) A8(10,-5) A9(8,-5) A10(6,-5) A11(4,-5) A15(-4,-5) A16(-6,-5) A17(-8,-5) A18(-10,-5) A19(-12,-5) A20(-14,-5) A21(-16,-5) A22(-18,-5) A23(-20,-5) A24(-22,-5) A25(-24,-5) B1(24,-3) B2(22,-3) B3(20,-3) B4(18,-3) B5(16,-3) B6(14,-3) B7(12,-3) B8(10,-3) B9(8,-3) B10(6,-3) B11(4,-3) B15(-4,-3) B16(-6,-3) B17(-8,-3) B18(-10,-3) B19(-12,-3) B20(-14,-3) B21(-16,-3) B22(-18,-3) B23(-20,-3) B24(-22,-3) B25(-24,-3) C1(24,-1) C2(22,-1) C3(20,-1) C4(18,-1) C5(16,-1) C6(14,-1) C7(12,-1) C8(10,-1) C9(8,-1) C10(6,-1) C11(4,-1) C15(-4,-1) C16(-6,-1) C17(-8,-1) C18(-10,-1) C19(-12,-1) C20(-14,-1) C21(-16,-1) C22(-18,-1) C23(-20,-1) C24(-22,-1) C25(-24,-1) D1(24,1) D2(22,1) D3(20,1) D4(18,1) D5(16,1) D6(14,1) D7(12,1) D8(10,1) D9(8,1) D10(6,1) D11(4,1) D15(-4,1) D16(-6,1) D17(-8,1) D18(-10,1) D19(-12,1) D20(-14,1) D21(-16,1) D22(-18,1) D23(-20,1) D24(-22,1) D25(-24,1) E1(24,3) E2(22,3) E3(20,3) E4(18,3) E5(16,3) E6(14,3) E7(12,3) E8(10,3) E9(8,3) E10(6,3) E11(4,3) E15(-4,3) E16(-6,3) E17(-8,3) E18(-10,3) E19(-12,3) E20(-14,3) E21(-16,3) E22(-18,3) E23(-20,3) E24(-22,3) E25(-24,3) F1(24,5) F3(20,5) F5(16,5) F7(12,5) F9(8,5) F11(4,5) F13(0,5) F15(-4,5) F17(-8,5) F19(-12,5) F21(-16,5) F23(-20,5) F25(-24,5)
  silkscreen extent -25,-6.5 25,6.1
POWER_CON [mm] "for power input"
  rect 3.8x3.8 hole 2.5: 1(0,0) 2(6.5,0) 3(3.25,4.5)
  silkscreen extent -1.98,-3.56 13.31,6.78
PQFP240 [mm] "240-Pin Plastic Quad Flat Pack (PQFP)"
  rect 1.5x0.3 smd: 1(-16.975,14.75) 2(-16.975,14.25) 3(-16.975,13.75) 4(-16.975,13.25) 5(-16.975,12.75) 6(-16.975,12.25) 7(-16.975,11.75) 8(-16.975,11.25) 9(-16.975,10.75) 10(-16.975,10.25) 11(-16.975,9.75) 12(-16.975,9.25) 13(-16.975,8.75) 14(-16.975,8.25) 15(-16.975,7.75) 16(-16.975,7.25) 17(-16.975,6.75) 18(-16.975,6.25) 19(-16.975,5.75) 20(-16.975,5.25) 21(-16.975,4.75) 22(-16.975,4.25) 23(-16.975,3.75) 24(-16.975,3.25) 25(-16.975,2.75) 26(-16.975,2.25) 27(-16.975,1.75) 28(-16.975,1.25) 29(-16.975,0.75) 30(-16.975,0.25) 31(-16.975,-0.25) 32(-16.975,-0.75) 33(-16.975,-1.25) 34(-16.975,-1.75) 35(-16.975,-2.25) 36(-16.975,-2.75) 37(-16.975,-3.25) 38(-16.975,-3.75) 39(-16.975,-4.25) 40(-16.975,-4.75) 41(-16.975,-5.25) 42(-16.975,-5.75) 43(-16.975,-6.25) 44(-16.975,-6.75) 45(-16.975,-7.25) 46(-16.975,-7.75) 47(-16.975,-8.25) 48(-16.975,-8.75) 49(-16.975,-9.25) 50(-16.975,-9.75) 51(-16.975,-10.25) 52(-16.975,-10.75) 53(-16.975,-11.25) 54(-16.975,-11.75) 55(-16.975,-12.25) 56(-16.975,-12.75) 57(-16.975,-13.25) 58(-16.975,-13.75) 59(-16.975,-14.25) 60(-16.975,-14.75) 121(16.975,-14.75) 122(16.975,-14.25) 123(16.975,-13.75) 124(16.975,-13.25) 125(16.975,-12.75) 126(16.975,-12.25) 127(16.975,-11.75) 128(16.975,-11.25) 129(16.975,-10.75) 130(16.975,-10.25) 131(16.975,-9.75) 132(16.975,-9.25) 133(16.975,-8.75) 134(16.975,-8.25) 135(16.975,-7.75) 136(16.975,-7.25) 137(16.975,-6.75) 138(16.975,-6.25) 139(16.975,-5.75) 140(16.975,-5.25) 141(16.975,-4.75) 142(16.975,-4.25) 143(16.975,-3.75) 144(16.975,-3.25) 145(16.975,-2.75) 146(16.975,-2.25) 147(16.975,-1.75) 148(16.975,-1.25) 149(16.975,-0.75) 150(16.975,-0.25) 151(16.975,0.25) 152(16.975,0.75) 153(16.975,1.25) 154(16.975,1.75) 155(16.975,2.25) 156(16.975,2.75) 157(16.975,3.25) 158(16.975,3.75) 159(16.975,4.25) 160(16.975,4.75) 161(16.975,5.25) 162(16.975,5.75) 163(16.975,6.25) 164(16.975,6.75) 165(16.975,7.25) 166(16.975,7.75) 167(16.975,8.25) 168(16.975,8.75) 169(16.975,9.25) 170(16.975,9.75) 171(16.975,10.25) 172(16.975,10.75) 173(16.975,11.25) 174(16.975,11.75) 175(16.975,12.25) 176(16.975,12.75) 177(16.975,13.25) 178(16.975,13.75) 179(16.975,14.25) 180(16.975,14.75)
  rect 0.3x1.5 smd: 61(-14.75,-16.975) 62(-14.25,-16.975) 63(-13.75,-16.975) 64(-13.25,-16.975) 65(-12.75,-16.975) 66(-12.25,-16.975) 67(-11.75,-16.975) 68(-11.25,-16.975) 69(-10.75,-16.975) 70(-10.25,-16.975) 71(-9.75,-16.975) 72(-9.25,-16.975) 73(-8.75,-16.975) 74(-8.25,-16.975) 75(-7.75,-16.975) 76(-7.25,-16.975) 77(-6.75,-16.975) 78(-6.25,-16.975) 79(-5.75,-16.975) 80(-5.25,-16.975) 81(-4.75,-16.975) 82(-4.25,-16.975) 83(-3.75,-16.975) 84(-3.25,-16.975) 85(-2.75,-16.975) 86(-2.25,-16.975) 87(-1.75,-16.975) 88(-1.25,-16.975) 89(-0.75,-16.975) 90(-0.25,-16.975) 91(0.25,-16.975) 92(0.75,-16.975) 93(1.25,-16.975) 94(1.75,-16.975) 95(2.25,-16.975) 96(2.75,-16.975) 97(3.25,-16.975) 98(3.75,-16.975) 99(4.25,-16.975) 100(4.75,-16.975) 101(5.25,-16.975) 102(5.75,-16.975) 103(6.25,-16.975) 104(6.75,-16.975) 105(7.25,-16.975) 106(7.75,-16.975) 107(8.25,-16.975) 108(8.75,-16.975) 109(9.25,-16.975) 110(9.75,-16.975) 111(10.25,-16.975) 112(10.75,-16.975) 113(11.25,-16.975) 114(11.75,-16.975) 115(12.25,-16.975) 116(12.75,-16.975) 117(13.25,-16.975) 118(13.75,-16.975) 119(14.25,-16.975) 120(14.75,-16.975) 181(14.75,16.975) 182(14.25,16.975) 183(13.75,16.975) 184(13.25,16.975) 185(12.75,16.975) 186(12.25,16.975) 187(11.75,16.975) 188(11.25,16.975) 189(10.75,16.975) 190(10.25,16.975) 191(9.75,16.975) 192(9.25,16.975) 193(8.75,16.975) 194(8.25,16.975) 195(7.75,16.975) 196(7.25,16.975) 197(6.75,16.975) 198(6.25,16.975) 199(5.75,16.975) 200(5.25,16.975) 201(4.75,16.975) 202(4.25,16.975) 203(3.75,16.975) 204(3.25,16.975) 205(2.75,16.975) 206(2.25,16.975) 207(1.75,16.975) 208(1.25,16.975) 209(0.75,16.975) 210(0.25,16.975) 211(-0.25,16.975) 212(-0.75,16.975) 213(-1.25,16.975) 214(-1.75,16.975) 215(-2.25,16.975) 216(-2.75,16.975) 217(-3.25,16.975) 218(-3.75,16.975) 219(-4.25,16.975) 220(-4.75,16.975) 221(-5.25,16.975) 222(-5.75,16.975) 223(-6.25,16.975) 224(-6.75,16.975) 225(-7.25,16.975) 226(-7.75,16.975) 227(-8.25,16.975) 228(-8.75,16.975) 229(-9.25,16.975) 230(-9.75,16.975) 231(-10.25,16.975) 232(-10.75,16.975) 233(-11.25,16.975) 234(-11.75,16.975) 235(-12.25,16.975) 236(-12.75,16.975) 237(-13.25,16.975) 238(-13.75,16.975) 239(-14.25,16.975) 240(-14.75,16.975)
  silkscreen extent -17.1,-15.83 15.83,15.83
PWP20 [mm] "PWP20;PSO;PWP (R-PDSO-G**);for TPS54310"
  rect 2x0.4 smd: 1(0,0)
  rect 2.032x3.81 smd: 1(3.302,-2.921)
  oval 2x0.4 smd: 2(0,-0.65) 3(0,-1.3) 4(0,-1.95) 5(0,-2.6) 6(0,-3.25) 7(0,-3.9) 8(0,-4.55) 9(0,-5.2) 10(0,-5.85)
  oval 2.2x0.4 smd: 11(6.6,-5.85) 12(6.6,-5.2) 13(6.6,-4.55) 14(6.6,-3.9) 15(6.6,-3.25) 16(6.6,-2.6) 17(6.6,-1.95) 18(6.6,-1.3) 19(6.6,-0.65) 20(6.6,0)
  silkscreen extent 2.08,-6.18 4.51,0.33
QFP44_2 [mm]
  oval 2.5x0.4 smd: 1(0,0)
  rect 2.5x0.4 smd: 2(0,-0.8) 3(0,-1.6) 4(0,-2.4) 5(0,-3.2) 6(0,-4) 7(0,-4.8) 8(0,-5.6) 9(0,-6.4) 10(0,-7.2) 11(0,-8) 23(12.9,-8) 24(12.9,-7.2) 25(12.9,-6.4) 26(12.9,-5.6) 27(12.9,-4.8) 28(12.9,-4) 29(12.9,-3.2) 30(12.9,-2.4) 31(12.9,-1.6) 32(12.9,-0.8) 33(12.9,0)
  rect 0.4x2.5 smd: 12(2.45,-10.45) 13(3.25,-10.45) 14(4.05,-10.45) 15(4.85,-10.45) 16(5.65,-10.45) 17(6.45,-10.45) 18(7.25,-10.45) 19(8.05,-10.45) 20(8.85,-10.45) 21(9.65,-10.45) 22(10.45,-10.45) 34(10.45,2.45) 35(9.65,2.45) 36(8.85,2.45) 37(8.05,2.45) 38(7.25,2.45) 39(6.45,2.45) 40(5.65,2.45) 41(4.85,2.45) 42(4.05,2.45) 43(3.25,2.45) 44(2.45,2.45)
  silkscreen extent 1.78,-8.67 11.12,0.66
R0603_4 [mil] "for ResPackX4____OK!"
  rect 35x18 smd: 1(0,0) 2(0,-36) 3(0,-72) 4(0,-108) 5(70.16,-108) 6(70.16,-72) 7(70.16,-36) 8(70.16,0)
  silkscreen extent -33,-123 99,15
RCA [mm]
  round 3.5 hole 2.1: 1(4.433,-1.168) 1(4.433,2.832) 2(-1.067,-1.168)
  silkscreen extent -6.91,-6.2 6.43,4.83
SMA [mm]
  round 3 hole 1.8: 1(0,0) 2(-2.5,-2.5) 2(-2.5,2.5) 2(2.5,-2.5) 2(2.5,2.5)
  silkscreen extent -4.5,-4.8 4.5,4.6
"SMD _LED" [mm]
  rect 1.3x1.6 smd: 1(0.95,0) 2(-0.95,0)
  silkscreen extent -2.13,-1.15 2,1.15
"SO-G3 for NPN" [mm]
  rect 0.9x1.27 smd: 1(0,1.25)
  rect 0.9x0.95 smd: 2(-0.95,-1.25) 3(0.95,-1.25)
  silkscreen extent -2.08,-1.37 1.3,1.25
SO-G8 [mm]
  rect 0.6x2.2 smd: 1(-1.905,-2.6) 2(-0.635,-2.6) 3(0.635,-2.6) 4(1.905,-2.6) 5(1.905,2.6) 6(0.635,2.6) 7(-0.635,2.6) 8(-1.905,2.6)
  silkscreen extent -2.88,-2.72 2.5,1.1
SOIC8 [mm] "8-Pin Small-Outline Integrated Circuit (SOIC)"
  rect 0.6x2.2 smd: 1(-1.905,-2.6) 2(-0.635,-2.6) 3(0.635,-2.6) 4(1.905,-2.6) 5(1.905,2.6) 6(0.635,2.6) 7(-0.635,2.6) 8(-1.905,2.6)
  silkscreen extent -2.88,-2.72 2.5,1.1
SOT23-5S [mil] "for TPS75733"
  oval 200x50 smd: 1(0,0) 2(0,-67) 3(0,-134) 4(0,-201) 5(0,-268)
  rect 400x400 smd: 3(375,-135)
  silkscreen extent 130,-360 580,95
SSOP48 [mm]
  rect 2x0.28 smd: 1(0,0)
  oval 2x0.28 smd: 2(0,-0.5) 3(0,-1) 4(0,-1.5) 5(0,-2) 6(0,-2.5) 7(0,-3) 8(0,-3.5) 9(0,-4) 10(0,-4.5) 11(0,-5) 12(0,-5.5) 13(0,-6) 14(0,-6.5) 15(0,-7) 16(0,-7.5) 17(0,-8) 18(0,-8.5) 19(0,-9) 20(0,-9.5) 21(0,-10) 22(0,-10.5) 23(0,-11) 24(0,-11.5) 25(8,-11.5) 26(8,-11) 27(8,-10.5) 28(8,-10) 29(8,-9.5) 30(8,-9) 31(8,-8.5) 32(8,-8) 33(8,-7.5) 34(8,-7) 35(8,-6.5) 36(8,-6) 37(8,-5.5) 38(8,-5) 39(8,-4.5) 40(8,-4) 41(8,-3.5) 42(8,-3) 43(8,-2.5) 44(8,-2) 45(8,-1.5) 46(8,-1) 47(8,-0.5) 48(8,0)
  silkscreen extent 1.84,-11.75 6.16,0.25
TSOP48 [mm] "for Am29LV800B"
  rect 2x0.3 smd: 1(0,0)
  oval 2x0.3 smd: 2(0,-0.5) 3(0,-1) 4(0,-1.5) 5(0,-2) 6(0,-2.5) 7(0,-3) 8(0,-3.5) 9(0,-4) 10(0,-4.5) 11(0,-5) 12(0,-5.5) 13(0,-6) 14(0,-6.5) 15(0,-7) 16(0,-7.5) 17(0,-8) 18(0,-8.5) 19(0,-9) 20(0,-9.5) 21(0,-10) 22(0,-10.5) 23(0,-11) 24(0,-11.5) 25(20.2,-11.5) 26(20.2,-11) 27(20.2,-10.5) 28(20.2,-10) 29(20.2,-9.5) 30(20.2,-9) 31(20.2,-8.5) 32(20.2,-8) 33(20.2,-7.5) 34(20.2,-7) 35(20.2,-6.5) 36(20.2,-6) 37(20.2,-5.5) 38(20.2,-5) 39(20.2,-4.5) 40(20.2,-4) 41(20.2,-3.5) 42(20.2,-3) 43(20.2,-2.5) 44(20.2,-2) 45(20.2,-1.5) 46(20.2,-1) 47(20.2,-0.5) 48(20.2,0)
  silkscreen extent 2.08,-11.75 18.12,0.25
TSOP86 [mm] "TSOP;43*2;for HY57V283220"
  rect 2x0.3 smd: 1(0,0)
  oval 2x0.3 smd: 2(0,-0.5) 3(0,-1) 4(0,-1.5) 5(0,-2) 6(0,-2.5) 7(0,-3) 8(0,-3.5) 9(0,-4) 10(0,-4.5) 11(0,-5) 12(0,-5.5) 13(0,-6) 14(0,-6.5) 15(0,-7) 16(0,-7.5) 17(0,-8) 18(0,-8.5) 19(0,-9) 20(0,-9.5) 21(0,-10) 22(0,-10.5) 23(0,-11) 24(0,-11.5) 25(0,-12) 26(0,-12.5) 27(0,-13) 28(0,-13.5) 29(0,-14) 30(0,-14.5) 31(0,-15) 32(0,-15.5) 33(0,-16) 34(0,-16.5) 35(0,-17) 36(0,-17.5) 37(0,-18) 38(0,-18.5) 39(0,-19) 40(0,-19.5) 41(0,-20) 42(0,-20.5) 43(0,-21) 44(11.938,-21) 45(11.938,-20.5) 46(11.938,-20) 47(11.938,-19.5) 48(11.938,-19) 49(11.938,-18.5) 50(11.938,-18) 51(11.938,-17.5) 52(11.938,-17) 53(11.938,-16.5) 54(11.938,-16) 55(11.938,-15.5) 56(11.938,-15) 57(11.938,-14.5) 58(11.938,-14) 59(11.938,-13.5) 60(11.938,-13) 61(11.938,-12.5) 62(11.938,-12) 63(11.938,-11.5) 64(11.938,-11) 65(11.938,-10.5) 66(11.938,-10) 67(11.938,-9.5) 68(11.938,-9) 69(11.938,-8.5) 70(11.938,-8) 71(11.938,-7.5) 72(11.938,-7) 73(11.938,-6.5) 74(11.938,-6) 75(11.938,-5.5) 76(11.938,-5) 77(11.938,-4.5) 78(11.938,-4) 79(11.938,-3.5) 80(11.938,-3) 81(11.938,-2.5) 82(11.938,-2) 83(11.938,-1.5) 84(11.938,-1) 85(11.938,-0.5) 86(11.938,0)
  silkscreen extent -0.23,-21.25 9.85,0.73

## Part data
C1 C2 C3 C4 C5 C6 C7 C8 C9 C10 C11 C12 C13 C14 C15 C16 C17 C18 C19 C20 C21 C22 C23 C24 C25 C26 C27 C28 C29 C30 C32 C36 C37 C38 C39 C40 C41 C42 C43 C44 C45 C46 C47 C48 C49 C50 C51 C52 C53 C54 C55 C56 C57 C58 C59 C60 C61 C62 C63 C64 C65 C66 C67 C68 C69 C70 C71 C72 C73 C74 C75 C76 C77 C78 C79 C80 C81 C82 C83 C84 C85 C86 C87 C88 C89 C90 C91 C92 C93 C94 C95 C96 C97 C98 C99 C100 C101 C102 C103 C104 C105 C106 C107 C108 C109 C110 C111 C112 C113 C114 C115 C116 C117 C118 C119 C120 C121 C122 C123 C124 C125 C126 C127 C128 C129 C130 C131 C132 C133 C153 C154 C155 C156 C157 C158 C159 C160 C161 C162 C163 C165 C166: "Capacitor"
C134 C135 C136 C137 C138 C139 C140 C141 C142 C143: "Polarized Capacitor (Radial)"
C144 C145 C146 C147 C148 C149 C150 C151 C152 C164: "Polarized Capacitor (Axial)"
DS1 DS2 DS3 DS4 DS5: "Typical RED, GREEN, YELLOW, AMBER GaAs LED"
DS6 DS7 DS9: "Typical BLUE SiC LED"
FB1 FB2 FB3: library part Inductor, "Inductor"
J1: library part "Header 7X2", "Header, 7-Pin, Dual row"
J2: "Z-Pack 2mm Hard Metric Type A 154 Position Male PCB Mount Connector"
J4: "RCA Connector"
JP1 JP2 JP7 JP8 JP9: "Header, 2-Pin"
JP3 JP4 JP5: library part "Header 5X2", "Header, 5-Pin, Dual row"
JP6: "Header, 10-Pin, Dual row"
JP10: "Header, 6-Pin, Dual row"
JP11: "Header, 2-Pin, Dual row"
L1: "Magnetic-Core Inductor"
Q1: library part QNPN, "NPN Bipolar Transistor"
R1 R2 R3 R4 R5 R6 R7 R8 R9 R10 R11 R12 R13 R14 R15 R16 R17 R18 R19 R20 R21 R22 R23 R24 R25 R26 R27 R28 R29 R39 R40 R41 R42 R43 R44 R45 R46 R53 R55 R56 R57 R58 R59 R60 R61 R62 R63 R64 R65 R66 R67 R68 R69 R70 R71 R72 R73 R74 R76 R77 R78 R79 R80 R81 R82 R83 R84 R86 R87 R88: "Resistor"
R30 R31 R32 R33 R34 R35 R36 R37 R38 R47 R48 R49 R50 R51 R52 R54: "Resistor Array - Parts"
S1: "DIP Switch"
S2: "Switch"
U2: "Cyclone Family, 1.5V FPGA, 173 I/O Pins, 2 x PLLs, Commercial Grade, Speed Grade 6"
U3: "Hotlink II"
U4 U6: library part Oscillator
U5: "EPCS1 Series, In-system programmable 3.3V configuration device, 8-Pin SOIC, 1-Megabit, Industrial Grade"
U8: "by TX"
U16 U17: library part "Volt Reg", "Voltage Regulator"
U20: library part "EMI filter"

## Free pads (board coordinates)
  round 50 hole 110: 1(4140,9717) 2(4140,6217)

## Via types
v1: diameter 16, hole 8, TopLayer to BottomLayer, 343 vias
v2: diameter 24, hole 12, TopLayer to BottomLayer, 84 vias
v3: diameter 56.69, hole 56.69, TopLayer to BottomLayer, 2 vias

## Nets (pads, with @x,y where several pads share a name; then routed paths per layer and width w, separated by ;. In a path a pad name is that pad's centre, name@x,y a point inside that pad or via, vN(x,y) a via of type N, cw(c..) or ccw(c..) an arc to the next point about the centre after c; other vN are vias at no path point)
1.4VPWRGD: R64.2 R72.2 U15.4 | length 690.6
  BottomLayer w10: 8732.77,9515.77 U15.4@8780,9515.77
  BottomLayer w12: R64.2@8240,9606.54 8233.46,9600 R72.2@8233.46,9480 8697,9480 8732.77,9515.77
101_BISTLE: U2.12 U3.E1 | length 741.1
  TopLayer w6: U3.E1@5690,6441.48 5753.48,6441.48 5825,6513 5825,7044.98 U2.12@5794.06,7076.93
101_BOE0: U2.14 U3.D1 | length 834.4
  TopLayer w6: U3.D1@5690,6402.11 5769.11,6402.11 5859,6492 5859,7067.66 U2.14@5821.89,7104.77
101_BOE1: U2.15 U3.D2 | length 924.9
  TopLayer w6: U3.D2@5650.63,6402.11 5670.74,6382 5770,6382 5876,6488 5876,7078.5 U2.15@5835.81,7118.68
101_DECOMDE: U2.8 U3.E2 | length 706
  TopLayer w6: U3.E2@5650.63,6441.48 5670.15,6461 5745,6461 5794,6510 5794,6965.63 U2.8@5738.38,7021.25
101_FRAMCHAR: U2.13 U3.D3 | length 876.2
  TopLayer w6: U3.D3@5611.26,6402.11 5630.15,6421 5763,6421 5842,6500 5842,7056.82 U2.13@5807.97,7090.85
101_INSEL: U2.195 U3.C10 | length 1493.8
  TopLayer w6: U2.195@4890.68,7550.19 4832,7491.5 4832,7012 4981.22,6862.78 4981.22,6591.78 5210.26,6362.74 U3.C10@5335.67,6362.74
101_L\F\I\: U2.227 U3.H4 | length 674.4
  TopLayer w6: v1(5298,7066.66) U2.227@5336.11,7104.77 ; v1(5552,6579.48) U3.H4@5571.89,6559.59
  BottomLayer w6: v1(5298,7066.66) 5298,6986 5552,6732 v1(5552,6579.48)
101_LPEN: U2.17 U3.C2 | length 1009.3
  TopLayer w6: U3.C2@5650.63,6362.74 5669.37,6344 5777,6344 5908,6475 5908,7102.18 U2.17@5863.65,7146.52
101_OELE: U2.6 U3.E3 | length 697.7
  TopLayer w6: U3.E3@5611.26,6441.48 v1(5630.78,6461) ; U2.6@5710.54,6993.41 v1(5766,6937.95)
  BottomLayer w6: v1(5630.78,6461) 5731,6461 5766,6496 v1(5766,6937.95)
101_PARCTL: U2.186 U3.C8 | length 1683.7
  TopLayer w6: v1(4713,7623.05) U2.186@4767.95,7678 ; v1(5395.15,6382) U3.C8@5414.41,6362.74
  BottomLayer w6: v1(4713,7623.05) 4713,7462 4860,7315 4860,7159 5254,6765 5254,6429 5301,6382 v1(5395.15,6382)
101_REFCLK+: R13.2 U2.201 | length 887
  TopLayer w6: U2.201@4979,7471.47 4899,7391.47 4899,7056 5099,6856 R13.2@5099,6700.46
101_REFCLK-: R12.2 U2.202 | length 897.7
  TopLayer w6: U2.202@4988.12,7452.75 4918,7382.63 4918,7063 5199,6782 R12.2@5199,6700.46
101_RFEN: U2.16 U3.C1 | length 918.7
  TopLayer w6: U3.C1@5690,6362.74 5772.74,6362.74 5891,6481 5891,7091.34 U2.16@5849.73,7132.6
101_RFMODE: U2.188 U3.C9 | length 1687.6
  TopLayer w6: U2.188@4793.25,7647.62 4751,7605.37 4751,7509 4807,7453 4807,7005 4958.9,6853.1 4958.9,6589.1 5204,6344 5356.3,6344 U3.C9@5375.04,6362.74
101_RXCKSEL: U2.200 U3.E9 | length 1377.2
  TopLayer w6: U2.200@4962.69,7483 4880,7400.31 4880,7045 5041.77,6883.23 5041.77,6610.23 5071.88,6580.12 5119.88,6580.12 5240,6460 5356.52,6460 U3.E9@5375.04,6441.48
101_RXCLK+: U2.233 U3.K4 | length 477.2
  TopLayer w6: U2.233@5419.62,7021.25 5382,6983.63 5382,6896 5571.89,6706.11 U3.K4@5571.89,6638.33
101_RXCLK-: U2.228 U3.J4 | length 607.8
  TopLayer w6: U2.228@5350.03,7090.85 5321,7061.82 5321,6937 5552,6706 5552,6618.85 U3.J4@5571.89,6598.96
101_RXCLKC+: U2.7 U3.C4 | length 839.8
  TopLayer w6: U3.C4@5571.89,6362.74 v1(5592.15,6383) ; U2.7@5731.22,7007.33 5726.67,7007.33 v1(5762,6972)
  BottomLayer w6: v1(5592.15,6383) 5612.15,6403 5740,6403 5789,6452 5789,6945 v1(5762,6972)
101_RXD0: U2.240 U3.H1 | length 456.6
  TopLayer w6: U2.240@5517.06,6923.81 5492,6898.75 5492,6873 5670,6695 5670,6579.59 U3.H1@5690,6559.59
101_RXD1: U2.1 U3.G2 | length 493
  TopLayer w6: U2.1@5640.94,6923.81 5725,6839.75 5725,6554 5710,6539 5669.41,6539 U3.G2@5650.63,6520.22
101_RXD2: U2.236 U3.H2 | length 533
  TopLayer w6: v1(5442,6893) 5422,6913 5422,6940.11 U2.236@5462.89,6981 ; v1(5630,6580.22) U3.H2@5650.63,6559.59
  BottomLayer w6: v1(5442,6893) 5630,6705 v1(5630,6580.22)
101_RXD3: U2.238 U3.J2 | length 442.9
  TopLayer w6: U2.238@5489.22,6951.65 5461,6923.43 5461,6862 5631,6692 5631,6618.59 U3.J2@5650.63,6598.96
101_RXD4: U2.239 U3.K2 | length 383
  TopLayer w6: U2.239@5503.14,6937.73 5476,6910.59 5476,6868 5650.63,6693.37 U3.K2@5650.63,6638.33
101_RXD5: U2.237 U3.G3 | length 561.3
  TopLayer w6: v1(5444,6920) 5444,6934.27 U2.237@5475.3,6965.57 ; U3.G3@5611.26,6520.22 v1(5634.04,6543)
  BottomLayer w6: v1(5444,6920) 5652,6712 5652,6560.96 v1(5634.04,6543)
101_RXD6: U2.235 U3.H3 | length 532.3
  TopLayer w6: v1(5418,6963.95) U2.235@5447.46,6993.41 ; v1(5592,6578.85) U3.H3@5611.26,6559.59
  BottomLayer w6: v1(5418,6963.95) 5410,6955.95 5410,6897 5591,6716 5591,6702 v1(5592,6578.85)
101_RXD7: U2.234 U3.J3 | length 516.3
  TopLayer w6: U2.234@5435.21,7009 5395,6968.79 5395,6907 5592,6710 5592,6618.22 U3.J3@5611.26,6598.96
